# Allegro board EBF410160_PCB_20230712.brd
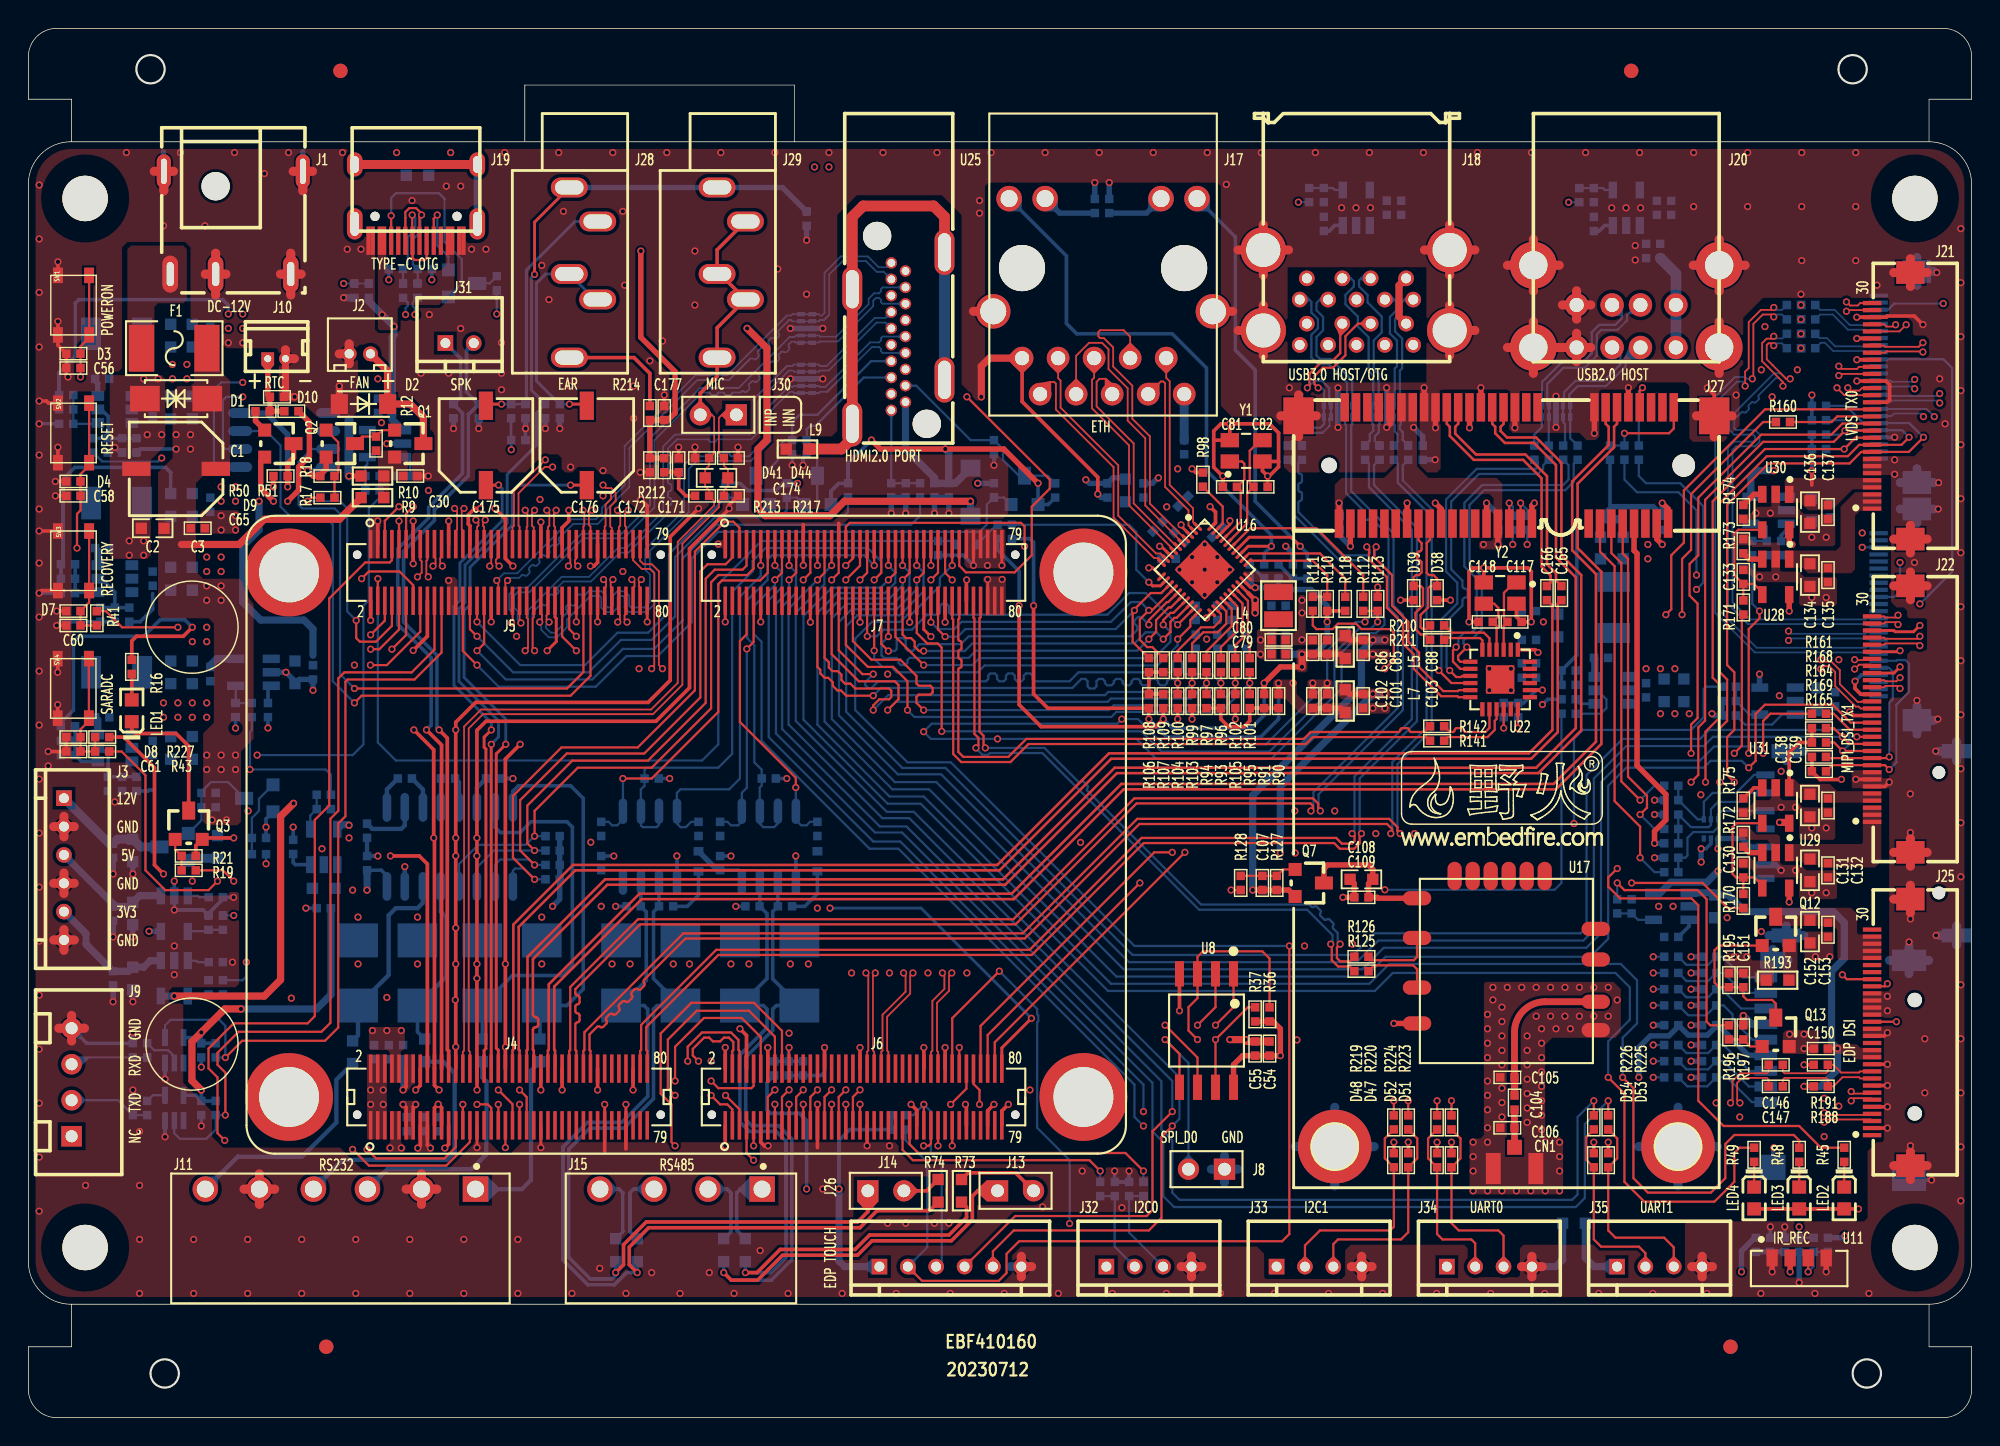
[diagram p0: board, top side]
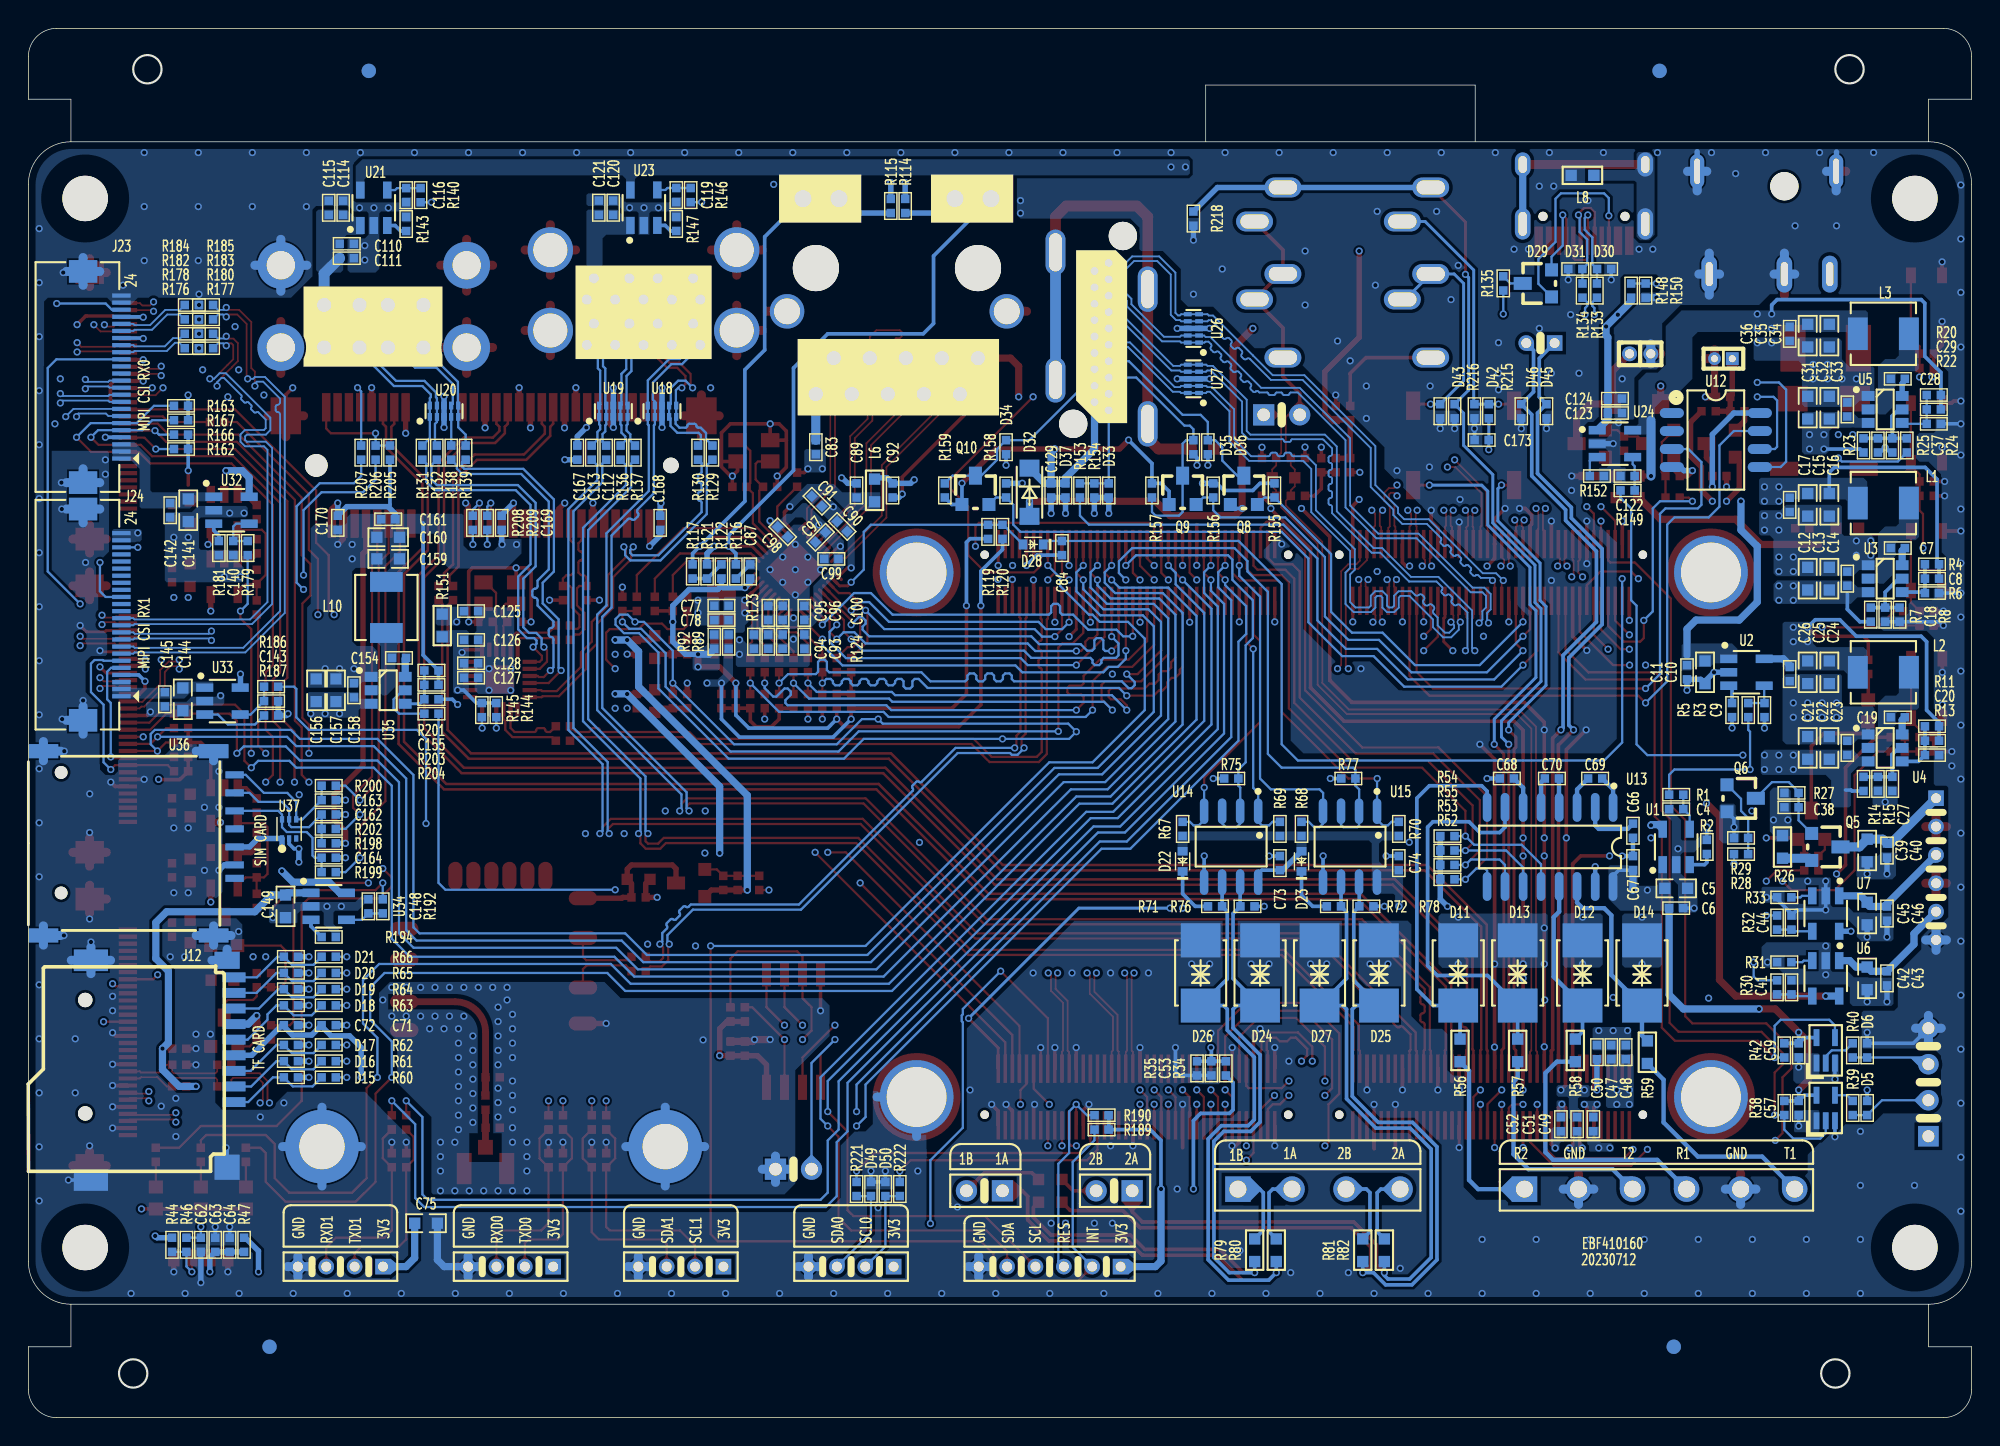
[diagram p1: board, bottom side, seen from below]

Outline 137 x 98 mm; copper layers: TOP, GND02, ART03, POW04, GND05, BOTTOM. Coordinates in mm from the lower left corner of the outline.
Outline path: circle c8.61,95.12 r1 ; circle c9.61,3.12 r1 ; circle c128.61,95.12 r1 ; circle c129.61,3.12 r1 ; 134,90 3,90 arc(0.88,89.12) 0,87 0,11 arc(0.88,8.88) 3,8 134,8 ; 134,90 134,93 137,93 137,96 arc(136.41,97.41) 135,98 2,98 arc(0.59,97.41) 0,96 0,93 3.05,93 3.05,90 ; 134,90 arc(136.12,89.12) 137,87 137,11 arc(136.12,8.88) 134,8 ; 3.05,8 3.05,5 0,5 0,2 arc(0.59,0.59) 2,0 135,0 arc(136.41,0.59) 137,2 137,5 134,5 134,8 ; 35,90 35,94 54,94 54,90

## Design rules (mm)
net group ANTENNA: nets N18056634 N18056637
net group B_DM1: nets B_DM1 HUB_DM1
net group B_DM2: nets B_DM2 HUB_DM2
net group B_DM3: nets B_DM3 HUB_DM3
net group B_DP1: nets B_DP1 HUB_DP1
net group B_DP2: nets B_DP2 HUB_DP2
net group B_DP3: nets B_DP3 HUB_DP3
net group DIFF_MDI0_PHY: nets MDIN0_PHY MDIP0_PHY
net group DIFF_MDI1_PHY: nets MDIN1_PHY MDIP1_PHY
net group DIFF_MDI2_PHY: nets MDIN2_PHY MDIP2_PHY
net group DIFF_MDI3_PHY: nets MDIN3_PHY MDIP3_PHY
net group DIFF_MIC: nets MIC_INN MIC_INP
net group DIFF_PCIE20_REFCLKP: nets PCIE20_REFCLKN PCIE20_REFCLKP
net group DIFF_PCIE20_RXP: nets PCIE20_RXN PCIE20_RXP
net group DIFF_USB3_HOST1_SSRX: nets USB3_HOST1_SSRXN USB3_HOST1_SSRXP
net group DM4: nets DM4 HUB_DM4
net group DP4: nets DP4 HUB_DP4
net group DSI0_TE: nets DSI0_TE N15774097
net group DSI1_TE: nets DSI1_TE N15772454
net group EDP_AUXN: nets EDP_AUXN EDP_TX_AUXN
net group EDP_AUXP: nets EDP_AUXP EDP_TX_AUXP
net group GMAC1_MCLKINOUT_M1: nets GMAC1_MCLKINOUT_M1 PHY_CLKOUT125
net group GMAC1_RXCLK_M1: nets GMAC1_RXCLK_M1 N15599549
net group GMAC1_RXD0_M1: nets GMAC1_RXD0_M1 N15599533
net group GMAC1_RXD1_M1: nets GMAC1_RXD1_M1 N15599537
net group GMAC1_RXD2_M1: nets GMAC1_RXD2_M1 N15599541
net group GMAC1_RXD3_M1: nets GMAC1_RXD3_M1 N15599545
net group GMAC1_RXDV_CRS_M1: nets GMAC1_RXDV_CRS_M1 N15599553
net group HOST1_DM: nets HOST1_DM USB3_HOST1_DM
net group HOST1_DP: nets HOST1_DP USB3_HOST1_DP
net group HP_DET: nets HP_DET N15830941
net group N17975561: nets N17975561 N18091011
net group OTG0_DM: nets OTG0_DM USB_OTG0_DM
net group OTG0_DP: nets OTG0_DP USB_OTG0_DP
net group PCIE20_CLKREQN_M0: nets N16823854 PCIE20_CLKREQN_M0
net group PCIE20_TXN: nets PCIE20_TXN PE_TXN
net group PCIE20_TXP: nets PCIE20_TXP PE_TXP
net group PCIE20_WAKEN_M0: nets N16811933 PCIE20_WAKEN_M0
net group PCIE_PWR_EN: nets N17592220 PCIE_PWR_EN
net group PWM3_IR: nets N17863087 PWM3_IR
net group SDMMC0_CLK: nets N16793151 SDMMC0_CLK
net group SDMMC0_CMD: nets N16793153 SDMMC0_CMD
net group SDMMC0_D0: nets N16793149 SDMMC0_D0
net group SDMMC0_D1: nets N16793157 SDMMC0_D1
net group SDMMC0_D2: nets N16793147 SDMMC0_D2
net group SDMMC0_D3: nets N16793155 SDMMC0_D3
net group SDMMC0_DET: nets N16793300 SDMMC0_DET
net group SIM_CLK0: nets N16980861 SIM_CLK0
net group SIM_DATA0: nets N16980863 SIM_DATA0
net group SIM_RST0: nets N16980859 SIM_RST0
net group SS_TXN: nets SS_TXN USB3_HOST1_SSTXN
net group SS_TXP: nets SS_TXP USB3_HOST1_SSTXP
net group USB2_HOST2_DM: nets N18057325 USB2_HOST2_DM
net group USB2_HOST2_DP: nets N18057335 USB2_HOST2_DP
net group USB2_HOST3_DM: nets N17770942 USB2_HOST3_DM
net group USB2_HOST3_DP: nets N17770939 USB2_HOST3_DP
net group 1V05_AVDD_PHY: nets 1V05_AVDD_PHY 1V05_DVDD_PHY 1V05_PHY
net group 3V3_DVDD_PHY: nets 3V3_DVDD_PHY N15599792 N15600759 N15605755
net group ANALOG: nets HP_SNS HPL_OUT HPR_OUT N15830872 N15838979 N15851038 SPKN_OUT SPKP_OUT
net group CSI_RX_D2N_S0: nets CSI_RX_D2N_S0 CSI_RX_D2N_S1 MIPI_CSI_RX_D2N
net group CSI_RX_D2P_S0: nets CSI_RX_D2P_S0 CSI_RX_D2P_S1 MIPI_CSI_RX_D2P
net group CSI_RX_D3N_S0: nets CSI_RX_D3N_S0 CSI_RX_D3N_S1 MIPI_CSI_RX_D3N
net group CSI_RX_D3P_S0: nets CSI_RX_D3P_S0 CSI_RX_D3P_S1 MIPI_CSI_RX_D3P
net group PWR: nets 3V3_OUT 3V3_WLAN 5V_OUT 12V_OUT HDMI_5V N17750554 N17759502 N17861933 SIM_VDD VCC_RTC

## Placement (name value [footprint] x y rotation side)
C1  220uF  [EC6P3]  10.41 66.93 270 top
C2  10uF  [C0603]  8.76 62.74 180 top
C3  0.1uF  [C0402]  11.94 62.74 0 top
C4  0.1uF  [C0402]  20.83 42.92 0 bottom
C5  10uF  [C0603]  20.83 37.34 180 bottom
C6  0.1uF  [C0402]  20.83 35.94 180 bottom
C7  0.1uF  [C0402]  5.21 61.34 0 bottom
C8  NC  [C0402]  2.79 59.18 0 bottom
C9  0.1uF  [C0402]  14.61 49.91 270 bottom
C10  10uF  [C0603]  18.8 52.58 270 bottom
C11  0.1uF  [C0402]  20.07 52.58 270 bottom
C12  10uF  [C0603]  11.56 59.18 90 bottom
C13  10uF  [C0603]  10.03 59.18 90 bottom
C14  0.1uF  [C0402]  8.76 59.18 90 bottom
C15  22uF  [C0603]  11.56 64.39 270 bottom
C16  22uF  [C0603]  10.03 64.39 270 bottom
C17  0.1uF  [C0402]  12.83 64.39 270 bottom
C18  NC  [C0402]  6.1 56.64 90 bottom
C19  0.1uF  [C0402]  5.21 49.4 0 bottom
C20  NC  [C0402]  2.79 47.75 0 bottom
C21  10uF  [C0603]  11.56 47.24 90 bottom
C22  10uF  [C0603]  10.03 47.24 90 bottom
C23  0.1uF  [C0402]  8.76 47.24 90 bottom
C24  22uF  [C0603]  10.03 52.58 270 bottom
C25  22uF  [C0603]  11.56 52.58 270 bottom
C26  0.1uF  [C0402]  12.83 52.45 270 bottom
C27  NC  [C0402]  5.59 44.7 90 bottom
C28  0.1uF  [C0402]  5.21 73.28 0 bottom
C29  NC  [C0402]  2.67 71.12 0 bottom
C30  0.1uF  [C0402]  26.92 66.42 0 top
C31  10uF  [C0603]  11.56 71.25 90 bottom
C32  10uF  [C0603]  10.03 71.25 90 bottom
C33  0.1uF  [C0402]  8.76 71.12 90 bottom
C34  22uF  [C0603]  10.03 76.33 270 bottom
C35  22uF  [C0603]  11.56 76.33 270 bottom
C36  0.1uF  [C0402]  12.83 76.45 270 bottom
C37  NC  [C0402]  5.59 68.58 90 bottom
C38  0.1uF  [C0402]  12.7 43.05 180 bottom
C39  10uF  [C0603]  7.37 40 270 bottom
C40  0.1uF  [C0402]  5.97 40 270 bottom
C41  0.1uF  [C0402]  12.7 30.35 90 bottom
C42  10uF  [C0603]  7.37 30.99 270 bottom
C43  0.1uF  [C0402]  5.97 30.99 270 bottom
C44  0.1uF  [C0402]  12.7 34.92 90 bottom
C45  10uF  [C0603]  7.37 35.56 270 bottom
C46  0.1uF  [C0402]  5.97 35.56 270 bottom
C47  0.1uF  [C0402]  25.4 25.78 90 bottom
C48  0.1uF  [C0402]  24.38 25.78 90 bottom
C49  0.1uF  [C0402]  26.67 20.7 270 bottom
C50  0.1uF  [C0402]  26.42 25.78 90 bottom
C51  0.1uF  [C0402]  27.81 20.7 90 bottom
C52  0.1uF  [C0402]  28.96 20.7 270 bottom
C53  1uF  [C0402]  53.59 24.64 270 bottom
C54  4.7uF  [C0402]  87.5 26.03 90 top
C55  0.1uF  [C0402]  86.49 26.03 90 top
C56  0.1uF  [C0402]  3.17 74.04 180 top
C57  0.1uF  [C0402]  12.19 21.84 270 bottom
C58  0.1uF  [C0402]  3.17 65.02 180 top
C59  0.1uF  [C0402]  12.19 25.91 270 bottom
C60  0.1uF  [C0402]  3.17 55.88 180 top
C61  0.1uF  [C0402]  3.17 46.99 180 top
C62  NC  [C0402]  124.84 12.19 270 bottom
C63  0.1uF  [C0402]  123.83 12.19 90 bottom
C64  1uF  [C0402]  122.81 12.19 90 bottom
C65  0.1uF  [C0402]  17.78 66.42 180 top
C66  0.1uF  [C0402]  23.88 41.4 270 bottom
C67  4.7uF  [C0402]  23.88 39.11 90 bottom
C68  0.1uF  [C0402]  32.77 45.08 0 bottom
C69  0.1uF  [C0402]  26.54 45.08 180 bottom
C70  0.1uF  [C0402]  29.59 45.08 180 bottom
C71  4.7uF  [C0402]  115.82 27.68 180 bottom
C72  0.1uF  [C0402]  118.49 27.68 180 bottom
C73  0.1uF  [C0402]  48.77 39.11 90 bottom
C74  0.1uF  [C0402]  40.39 39.11 90 bottom
C75  10uF  [C0603]  108.97 13.71 180 bottom
C77  0.1uF  [C0402]  88.14 57.28 0 bottom
C78  4.7uF  [C0402]  88.14 56.26 0 bottom
C79  0.1uF  [C0402]  88.14 53.85 0 top
C80  4.7uF  [C0402]  88.14 54.86 0 top
C81  18pF  [C0402]  84.71 65.66 180 top
C82  18pF  [C0402]  86.87 65.66 0 top
C83  0.1uF  [C0402]  81.48 68.45 270 bottom
C84  0.1uF  [C0402]  64.14 61.34 270 bottom
C85  4.7uF  [C0402]  91.57 54.35 90 top
C86  0.1uF  [C0402]  90.55 54.35 90 top
C87  0.1uF  [C0402]  86.11 59.69 90 bottom
C88  0.1uF  [C0402]  94.11 54.35 270 top
C89  4.7uF  [C0402]  78.61 65.4 90 bottom
C90  0.1uF  [C0402]  79.63 62.86 45 bottom
C91  0.1uF  [C0402]  81.41 64.64 225 bottom
C92  0.1uF  [C0402]  76.07 65.4 270 bottom
C93  4.7uF  [C0402]  83.82 54.74 270 bottom
C94  0.1uF  [C0402]  84.84 54.74 270 bottom
C95  0.1uF  [C0402]  84.84 56.77 90 bottom
C96  4.7uF  [C0402]  83.82 56.77 90 bottom
C97  0.1uF  [C0402]  81.15 62.1 315 bottom
C98  0.1uF  [C0402]  83.82 62.48 225 bottom
C99  0.1uF  [C0402]  80.39 60.58 0 bottom
C100  4.7uF  [C0402]  82.3 56.77 90 bottom
C101  4.7uF  [C0402]  91.57 50.54 90 top
C102  0.1uF  [C0402]  90.55 50.54 90 top
C103  0.1uF  [C0402]  94.11 50.54 270 top
C104  10pF  [C0402]  104.78 22.22 270 top
C105  NC  [C0402]  104.27 24 180 top
C106  NC  [C0402]  104.27 20.45 180 top
C107  0.1uF  [C0402]  87 37.72 90 top
C108  10uF  [C0603]  93.98 37.97 180 top
C109  0.1uF  [C0402]  93.98 36.7 180 top
C110  1uF  [C0402]  114.55 82.8 180 bottom
C111  1uF  [C0402]  114.55 81.79 180 bottom
C112  0.1uF  [C0402]  96.27 68.07 270 bottom
C113  0.1uF  [C0402]  97.28 68.07 270 bottom
C114  10uF  [C0402]  114.81 85.34 90 bottom
C115  0.1uF  [C0402]  115.82 85.34 90 bottom
C116  0.1uF  [C0402]  110.36 86.23 270 bottom
C117  NC  [C0402]  104.78 56.13 0 top
C118  NC  [C0402]  102.74 56.13 0 top
C119  0.1uF  [C0402]  91.32 86.24 270 bottom
C120  10uF  [C0402]  95.77 85.35 90 bottom
C121  0.1uF  [C0402]  96.78 85.35 90 bottom
C122  0.1uF  [C0402]  24.26 66.42 0 bottom
C123  10uF  [C0402]  25.15 70.86 180 bottom
C124  0.1uF  [C0402]  25.15 71.88 180 bottom
C125  0.1uF  [C0402]  105.79 56.89 180 bottom
C126  4.7uF  [C0402]  105.79 54.86 180 bottom
C127  0.1uF  [C0402]  105.79 52.2 180 bottom
C128  0.1uF  [C0402]  105.79 53.21 180 bottom
C129  1uF  [C0402]  64.9 65.4 270 bottom
C130  0.1uF  [C0402]  120.9 38.61 90 top
C131  10uF  [C0603]  125.6 38.61 270 top
C132  0.1uF  [C0402]  126.87 38.61 270 top
C133  0.1uF  [C0402]  120.9 59.31 90 top
C134  10uF  [C0603]  125.6 59.43 270 top
C135  0.1uF  [C0402]  126.87 59.43 270 top
C136  10uF  [C0603]  125.6 63.88 270 top
C137  0.1uF  [C0402]  126.87 63.88 270 top
C138  10uF  [C0603]  125.6 43.18 270 top
C139  0.1uF  [C0402]  126.87 43.18 270 top
C140  0.1uF  [C0402]  122.56 61.34 270 bottom
C141  10uF  [C0603]  125.73 64.01 270 bottom
C142  0.1uF  [C0402]  127 64.01 270 bottom
C143  0.1uF  [C0402]  119.89 50.54 180 bottom
C144  10uF  [C0603]  126.11 50.67 270 bottom
C145  0.1uF  [C0402]  127.38 50.67 270 bottom
C146  0.1uF  [C0402]  123.19 24.89 0 top
C147  0.1uF  [C0402]  123.19 23.37 0 top
C148  0.1uF  [C0402]  113.03 36.07 90 bottom
C149  10uF  [C0603]  118.87 36.07 270 bottom
C150  0.1uF  [C0402]  126.36 26.03 180 top
C151  0.1uF  [C0402]  120.9 30.86 270 top
C152  10uF  [C0603]  125.6 34.29 270 top
C153  0.1uF  [C0402]  126.87 34.42 270 top
C154  0.1uF  [C0402]  110.87 53.59 0 bottom
C155  NC  [C0402]  108.58 51.69 0 bottom
C156  10uF  [C0603]  116.71 51.31 90 bottom
C157  10uF  [C0603]  115.32 51.31 90 bottom
C158  0.1uF  [C0402]  114.05 51.31 90 bottom
C159  22uF  [C0603]  111.63 60.58 0 bottom
C160  22uF  [C0603]  111.63 62.1 0 bottom
C161  0.1uF  [C0402]  111.63 63.37 0 bottom
C162  33pF  [C0402]  115.82 42.54 180 bottom
C163  33pF  [C0402]  115.82 43.56 180 bottom
C164  33pF  [C0402]  115.82 39.5 180 bottom
C165  0.1uF  [C0402]  108.08 58.16 90 top
C166  0.1uF  [C0402]  107.06 58.16 90 top
C167  0.1uF  [C0402]  98.3 68.07 270 bottom
C168  0.1uF  [C0402]  92.46 63.12 270 bottom
C169  4.7uF  [C0402]  103.63 63.12 90 bottom
C170  4.7uF  [C0402]  115.19 63.12 270 bottom
C171  1uF  [C0402]  45.85 67.18 90 top
C172  0.1uF  [C0402]  43.81 67.18 270 top
C173  1uF  [C0402]  34.54 68.96 0 bottom
C174  100pF  [C0603]  48.51 66.29 0 top
C175  220uF  [EC6P3]  32.26 68.58 180 top
C176  220uF  [EC6P3]  39.37 68.58 180 top
C177  0.1uF  [C0402]  44.83 70.86 90 top
CN1  WiFi-Ant  [UFL-3]  104.78 17.57 180 top
D1  SMAJ13CA  [SMA214-CA]  10.41 71.88 180 top
D2  1N4148W  [SOD-123]  23.62 71.5 0 top
D3  KLXES15AAA1  [ES0402]  3.17 75.06 0 top
D4  KLXES15AAA1  [ES0402]  3.17 66.04 0 top
D5  KLXES15AAA1  [ES0402]  7.37 21.84 270 bottom
D6  KLXES15AAA1  [ES0402]  7.37 25.91 270 bottom
D7  KLXES15AAA1  [ES0402]  3.17 56.89 0 top
D8  KLXES15AAA1  [ES0402]  3.17 48 0 top
D9  BAT54C  [SOT23]  17.65 68.71 270 top
D10  KLXES15AAA1  [ES0402]  17.53 72.01 180 top
D11  SMBJ15CA  [SMB-CA]  36.2 31.37 270 bottom
D12  SMBJ15CA  [SMB-CA]  27.43 31.37 270 bottom
D13  SMBJ15CA  [SMB-CA]  32 31.37 270 bottom
D14  SMBJ15CA  [SMB-CA]  23.24 31.37 270 bottom
D15  KLXES15AAA1  [ES0402]  118.49 24 0 bottom
D16  KLXES15AAA1  [ES0402]  118.49 25.14 0 bottom
D17  KLXES15AAA1  [ES0402]  118.49 26.29 0 bottom
D18  KLXES15AAA1  [ES0402]  118.49 29.08 0 bottom
D19  KLXES15AAA1  [ES0402]  118.49 30.22 0 bottom
D20  KLXES15AAA1  [ES0402]  118.49 31.37 0 bottom
D21  KLXES15AAA1  [ES0402]  118.49 32.51 0 bottom
D22  RB521S-30  [SOD523]  55.63 39.24 90 bottom
D23  RB521S-30  [SOD523]  47.24 39.24 90 bottom
D24  SMBJ6.5CA  [SMB-CA]  50.16 31.37 270 bottom
D25  SMBJ6.5CA  [SMB-CA]  41.78 31.37 270 bottom
D26  SMBJ6.5CA  [SMB-CA]  54.36 31.37 270 bottom
D27  SMBJ6.5CA  [SMB-CA]  45.97 31.37 270 bottom
D28  RB521S-30  [SOD523]  66.17 61.59 0 bottom
D29  BAT54A  [SOT23]  30.61 80.01 90 bottom
D30  KLXES15AAA1  [ES0402]  25.91 81.02 0 bottom
D31  KLXES15AAA1  [ES0402]  27.94 81.02 180 bottom
D32  1N5819W  [SOD-123]  66.42 65.28 90 bottom
D33  KLXES15AAA1  [ES0402]  60.83 65.4 90 bottom
D34  KLXES15AAA1  [ES0402]  68.07 68.45 90 bottom
D35  KLXES15AAA1  [ES0402]  54.86 68.45 90 bottom
D36  KLXES15AAA1  [ES0402]  53.85 68.45 90 bottom
D37  KLXES15AAA1  [ES0402]  63.88 65.4 90 bottom
D38  KLXES15AAA1  [ES0402]  99.31 58.16 90 top
D39  KLXES15AAA1  [ES0402]  97.66 58.16 90 top
D41  KLXES15AAA1  [ES0402]  47.5 67.69 0 top
D42  KLXES15AAA1  [ES0402]  35.05 70.99 90 bottom
D43  KLXES15AAA1  [ES0402]  37.47 70.99 90 bottom
D44  KLXES15AAA1  [ES0402]  49.53 67.69 180 top
D45  KLXES15AAA1  [ES0402]  29.97 70.99 90 bottom
D46  KLXES15AAA1  [ES0402]  31.75 70.99 90 bottom
D47  KLXES15AAA1  [ES0402]  97.28 18.16 270 top
D48  KLXES15AAA1  [ES0402]  96.27 18.16 270 top
D49  KLXES15AAA1  [ES0402]  77.6 16.13 270 bottom
D50  KLXES15AAA1  [ES0402]  76.58 16.13 270 bottom
D51  KLXES15AAA1  [ES0402]  100.33 18.16 270 top
D52  KLXES15AAA1  [ES0402]  99.31 18.16 270 top
D53  KLXES15AAA1  [ES0402]  111.38 18.16 270 top
D54  KLXES15AAA1  [ES0402]  110.36 18.16 270 top
F1  SMD1812P200TF16  [F1812]  10.29 75.44 0 top
H1  -  [NPTH_M3]  4 86 0 top
H2  -  [NPTH_M3]  4 12 0 top
H3  -  [NPTH_M3]  133 12 0 top
H4  -  [NPTH_M3]  133 86 0 top
J1  DC-044A-20A  [DC_IN_TH_3P_10R1X11R6]  14.45 85.16 270 top
J2  A1501WV-2P  [ZH1P5MM_TH_2P]  23.37 75.04 180 top
J3  PH-6A  [PH-1X6-2P0]  2.51 38.69 270 top
J4  -  [SGDBM-05-80P-H10]  33.88 22.62 0 top
J5  -  [SGDBF-05-80P-H30]  33.88 59.62 180 top
J6  -  [SGDBM-05-80P-H10]  58.88 22.62 0 top
J7  -  [SGDBF-05-80P-H30]  58.88 59.62 180 top
J8  1X2PIN-M  [DIP-1X2-2P54]  83.06 17.52 180 top
J9  XH-4A  [XH2P54-4P]  3.05 23.66 90 top
J10  1.25T-2A  [GH1P25_TH_2P]  17.5 74.7 0 top
J11  CON6  [DB2ERC-3P81-6P]  22 16.12 180 top
J12  TF_Card  [TFCARD]  132.99 25.46 270 bottom
J13  1X2PIN-M  [DIP-1X2-2P54]  69.6 16 0 top
J14  1X2PIN-M  [DIP-1X2-2P54]  60.45 16 0 top
J15  WJ15EDGRC-3.81-4P  [DB2ERC-3P81-4P]  46.01 16.12 180 top
J17  -  [HY911130A]  75.77 81.09 0 top
J18  USB3D0_USB2D0-A-D  [USB3D0-AF-18P]  93.63 78.87 180 top
J19  TYPE-C  [TYPE-C-31-M-12]  27.33 83.3 180 top
J20  -  [USB-A-D]  112.65 81.99 0 top
J21  FPC_0R5_30P_D  [FPC-30P-0P5]  131.33 71.37 90 top
J22  FPC_0R5_30P_D  [FPC-30P-0P5]  131.33 49.27 90 top
J23  FPC_0P5_24P_D  [FPC_24P_0P5]  131.79 73.41 90 bottom
J24  FPC_0P5_24P_D  [FPC_24P_0P5]  131.79 56.64 90 bottom
J25  FPC_0R5_30P_D  [FPC-30P-0P5]  131.33 27.18 90 top
J26  PH-6A  [PH-1X6-2P0]  65 10.65 0 top
J27  MINI-PCIE  [PCIE_52P]  104.2 67.17 180 top
J28  PJ-325C5-G  [EAR_JACK]  39.04 80.68 270 top
J29  PJ-325C5-R  [EAR_JACK]  49.45 80.68 270 top
J30  1X2PIN-M  [DIP-1X2-2P54]  48.64 70.74 180 top
J31  PH  [PH-1X2-2P0_L]  30.4 75.8 0 top
J32  PH-4A  [PH-1X4-2P0]  79 10.65 0 top
J33  PH-4A  [PH-1X4-2P0]  91 10.65 0 top
J34  PH-4A  [PH-1X4-2P0]  103 10.65 0 top
J35  PH-4A  [PH-1X4-2P0]  115 10.65 0 top
L1  3.3uH  [L4520]  6.22 64.51 0 bottom
L2  3.3uH  [L4520]  6.22 52.58 0 bottom
L3  3.3uH  [L4520]  6.22 76.45 0 bottom
L4  2.2uH  [L2520]  88.14 57.28 270 top
L5  100R 100MHz  [L0603]  92.84 54.35 90 top
L6  100R 100MHz  [L0603]  77.34 65.4 90 bottom
L7  100R 100MHz  [L0603]  92.84 50.54 90 top
L8  120R 100MHz  [L0603]  27.43 87.63 0 bottom
L9  330R 100MHz  [L0603]  54.23 68.32 180 top
L10  3.3uH  [L4520]  111.76 57.15 90 bottom
LED1  RED  [LED0603]  7.29 49.86 270 top
LED2  BLUE  [LED0603]  128.02 15.49 90 top
LED3  BLUE  [LED0603]  124.84 15.49 90 top
LED4  BLUE  [LED0603]  121.67 15.49 90 top
NOREF  -  []  0 49 0 top
NOREF#2  -  []  0.51 38.69 90 top
NOREF#3  -  []  136.49 73.41 90 top
NOREF#4  -  []  15.38 41.12 90 top
NOREF#5  -  []  68.5 8 90 top
NOREF#6  -  []  0.51 23.66 90 top
NOREF#7  -  []  68.5 0 90 top
NOREF#8  -  [unnamed#2]  113 95 0 top
NOREF#9  -  []  4 12 0 top
NOREF#10  -  []  0 49 0 top
NOREF#11  -  []  6.83 8 90 top
NOREF#12  -  []  0 49 0 top
NOREF#13  -  []  135.98 71.38 90 top
NOREF#14  -  []  0 13.6 0 top
NOREF#15  -  []  135.98 49.28 90 top
NOREF#16  -  []  122.49 31.06 90 top
NOREF#17  -  []  0 14.29 0 top
NOREF#18  -  []  134.57 12.28 0 top
NOREF#19  -  []  0 49 0 top
NOREF#20  -  []  0 49 0 top
NOREF#21  -  []  135.98 27.18 90 top
NOREF#22  -  []  0 49 0 top
NOREF#23  -  []  0 14.83 0 top
NOREF#24  -  []  4 12 0 top
NOREF#25  -  []  122.46 45.34 90 top
NOREF#26  -  []  0 78.37 0 top
NOREF#27  -  []  0 49 0 top
NOREF#28  -  []  0 -0.29 0 top
NOREF#29  -  []  4 12 90 top
NOREF#30  -  []  0 49 0 top
NOREF#31  -  [unnamed#2]  120 5 0 top
NOREF#32  -  []  0 12.03 0 top
NOREF#33  -  []  22.08 0 90 top
NOREF#34  -  []  0 13.88 0 top
NOREF#35  -  [unnamed#2]  22 95 0 top
NOREF#36  -  []  0 16.34 0 top
NOREF#37  -  []  0 78.12 0 top
NOREF#38  -  []  68.5 8 90 top
NOREF#39  -  []  136.23 9 0 top
NOREF#40  -  []  0 17.63 0 top
NOREF#41  -  []  0 49 0 top
NOREF#42  -  []  136.49 56.64 90 top
NOREF#43  -  [unnamed#2]  21 5 0 top
NOREF#44  -  []  133 12 90 top
NOREF#45  -  []  0 49 0 top
NOREF#46  -  [unnamed#2]  113 95 180 bottom
NOREF#47  -  [unnamed#2]  120 5 180 bottom
NOREF#48  -  [unnamed#2]  21 5 180 bottom
NOREF#49  -  [unnamed#2]  22 95 180 bottom
Q1  AO3407  [SOT23]  26.81 68.71 270 top
Q2  SS8050  [SOT23]  21.98 68.71 270 top
Q3  SS8050  [SOT23]  11.3 41.78 0 top
Q5  AO3407  [SOT23]  10.29 40.26 270 bottom
Q6  SS8050  [SOT23]  16.26 43.69 270 bottom
Q7  AO3407  [SOT23]  90.3 37.72 270 top
Q8  2SK3018  [SOT23]  51.31 65.4 180 bottom
Q9  2SK3018  [SOT23]  55.63 65.4 180 bottom
Q10  2SK3018  [SOT23]  70.23 65.4 180 bottom
Q12  AO3407  [SOT23]  123.19 34.29 0 top
Q13  SS8050  [SOT23]  123.19 27.18 0 top
R1  1K  [R0402]  20.83 43.94 180 bottom
R2  3.4K  [R0402]  18.67 40.26 90 bottom
R3  1K  [R0402]  15.75 49.91 90 bottom
R4  100K  [R0402]  2.79 60.2 0 bottom
R5  6.8K  [R0402]  16.89 49.91 270 bottom
R6  30K  [R0402]  2.79 58.16 180 bottom
R7  140K  [R0402]  7.11 56.64 90 bottom
R8  20K  [R0402]  5.08 56.64 270 bottom
R9  NC  [R0603]  24.26 64.9 0 top
R10  0R  [R0603]  24.26 66.42 0 top
R11  115K  [R0402]  2.79 48.77 0 bottom
R12  20K  [R0402]  24.51 68.71 90 top
R13  20K  [R0402]  2.79 46.73 180 bottom
R14  140K  [R0402]  7.62 44.7 90 bottom
R15  20K  [R0402]  6.6 44.7 270 bottom
R16  4.7K  [R0402]  7.29 52.96 270 top
R17  1K  [R0402]  21.08 64.9 0 top
R18  10K  [R0402]  21.08 66.42 180 top
R19  1K  [R0402]  11.3 38.61 180 top
R20  115K  [R0402]  2.67 72.13 0 bottom
R21  10K  [R0402]  11.3 39.62 0 top
R22  20K  [R0402]  2.67 70.1 180 bottom
R23  NC  [R0402]  7.62 68.58 90 bottom
R24  1K  [R0402]  4.57 68.58 90 bottom
R25  NC  [R0402]  6.6 68.58 270 bottom
R26  0R  [R0603]  13.34 40.26 270 bottom
R27  20K  [R0402]  12.7 44.07 180 bottom
R28  510R  [R0402]  16.26 39.75 180 bottom
R29  10K  [R0402]  16.26 40.89 0 bottom
R30  1K  [R0402]  13.72 30.35 270 bottom
R31  6.8K  [R0402]  13.21 32.13 0 bottom
R32  1K  [R0402]  13.72 34.92 270 bottom
R33  6.8K  [R0402]  13.21 36.7 0 bottom
R34  15K  [R0402]  52.58 24.64 90 bottom
R35  10K  [R0402]  54.61 24.64 270 bottom
R36  10K  [R0402]  87.5 28.45 90 top
R37  10K  [R0402]  86.49 28.45 90 top
R38  10K  [R0402]  13.21 21.84 270 bottom
R39  510R  [R0402]  8.38 21.84 90 bottom
R40  510R  [R0402]  8.38 25.91 90 bottom
R41  100R  [R0402]  4.83 56.39 90 top
R42  10K  [R0402]  13.21 25.91 270 bottom
R43  100R  [R0402]  5.21 46.99 0 top
R44  10K  [R0402]  126.87 12.19 270 bottom
R45  470R  [R0402]  128.02 18.54 90 top
R46  22R  [R0402]  125.86 12.19 270 bottom
R47  22R  [R0402]  121.79 12.19 90 bottom
R48  470R  [R0402]  124.84 18.54 90 top
R49  470R  [R0402]  121.67 18.54 90 top
R50  0R  [R0402]  16.51 70.99 0 top
R51  NC  [R0402]  18.54 70.99 0 top
R52  10K  [R0402]  36.96 37.97 180 bottom
R53  10K  [R0402]  36.96 38.99 180 bottom
R54  10K  [R0402]  36.96 41.02 180 bottom
R55  10K  [R0402]  36.96 40 180 bottom
R56  0R  [R0603]  36.07 25.91 270 bottom
R57  0R  [R0603]  32 25.91 270 bottom
R58  0R  [R0603]  27.94 25.91 270 bottom
R59  0R  [R0603]  22.86 25.78 270 bottom
R60  22R  [R0402]  115.82 24 0 bottom
R61  22R  [R0402]  115.82 25.14 0 bottom
R62  22R  [R0402]  115.82 26.29 0 bottom
R63  22R  [R0402]  115.82 29.08 0 bottom
R64  22R  [R0402]  115.82 30.22 0 bottom
R65  22R  [R0402]  115.82 31.37 0 bottom
R66  0R  [R0402]  115.82 32.51 0 bottom
R67  10K  [R0402]  55.63 41.53 90 bottom
R68  10K  [R0402]  47.24 41.53 90 bottom
R69  10K  [R0402]  48.77 41.53 90 bottom
R70  10K  [R0402]  40.39 41.53 90 bottom
R71  4.7K  [R0402]  53.34 36.07 180 bottom
R72  4.7K  [R0402]  44.96 36.07 180 bottom
R73  120R  [R0603]  65.79 16 90 top
R74  120R  [R0603]  64.14 16 90 top
R75  10K  [R0402]  52.2 45.08 0 bottom
R76  4.7K  [R0402]  51.05 36.07 180 bottom
R77  10K  [R0402]  43.94 45.08 0 bottom
R78  4.7K  [R0402]  42.67 36.07 180 bottom
R79  0R  [R0603]  50.55 11.81 90 bottom
R80  0R  [R0603]  49.02 11.81 90 bottom
R81  0R  [R0603]  42.93 11.81 90 bottom
R82  0R  [R0603]  41.4 11.81 90 bottom
R89  NC  [R0402]  87.63 54.74 270 bottom
R90  NC  [R0402]  88.14 50.54 270 top
R91  0R  [R0402]  87.12 50.54 90 top
R92  0R  [R0402]  88.65 54.74 270 bottom
R93  4.7K  [R0402]  84.07 50.54 90 top
R94  4.7K  [R0402]  83.06 50.54 90 top
R95  4.7K  [R0402]  86.11 50.54 90 top
R96  22R  [R0402]  84.07 53.08 90 top
R97  22R  [R0402]  83.06 53.08 90 top
R98  2.49K  [R0402]  82.8 66.17 90 top
R99  22R  [R0402]  82.04 53.08 90 top
R100  22R  [R0402]  81.03 53.08 90 top
R101  22R  [R0402]  86.11 53.08 90 top
R102  22R  [R0402]  85.09 53.08 90 top
R103  4.7K  [R0402]  82.04 50.54 270 top
R104  4.7K  [R0402]  81.03 50.54 270 top
R105  4.7K  [R0402]  85.09 50.54 270 top
R106  NC  [R0402]  78.99 50.54 90 top
R107  0R  [R0402]  80.01 50.54 270 top
R108  4.7K  [R0402]  78.99 53.08 90 top
R109  4.7K  [R0402]  80.01 53.08 90 top
R110  4.7K  [R0402]  91.57 57.4 90 top
R111  NC  [R0402]  90.55 57.4 90 top
R112  0R  [R0402]  94.11 57.4 90 top
R113  NC  [R0402]  95.12 57.4 90 top
R114  510R  [R0402]  75.18 85.47 90 bottom
R115  510R  [R0402]  76.2 85.47 90 bottom
R116  4.7K  [R0402]  87.12 59.69 270 bottom
R117  4.7K  [R0402]  90.17 59.69 270 bottom
R118  4.7K  [R0402]  92.84 57.4 270 top
R119  NC  [R0402]  69.34 62.48 90 bottom
R120  10K  [R0402]  68.33 62.48 90 bottom
R121  0R  [R0402]  89.15 59.69 270 bottom
R122  NC  [R0402]  88.14 59.69 270 bottom
R123  0R  [R0402]  85.85 54.74 270 bottom
R124  0R  [R0402]  82.3 54.74 90 bottom
R125  2.2R  [R0402]  93.98 31.49 0 top
R126  2.2R  [R0402]  93.98 32.51 0 top
R127  10K  [R0402]  88.01 37.72 90 top
R128  510R  [R0402]  85.47 37.72 90 top
R129  2.2R  [R0402]  88.77 68.07 270 bottom
R130  2.2R  [R0402]  89.79 68.07 270 bottom
R131  2.2R  [R0402]  109.22 68.07 270 bottom
R132  2.2R  [R0402]  108.2 68.07 270 bottom
R133  2.2R  [R0402]  26.42 79.5 270 bottom
R134  2.2R  [R0402]  27.43 79.5 270 bottom
R135  100R  [R0402]  33.02 80.01 270 bottom
R136  2.2R  [R0402]  95.25 68.07 270 bottom
R137  2.2R  [R0402]  94.23 68.07 270 bottom
R138  2.2R  [R0402]  107.19 68.07 270 bottom
R139  2.2R  [R0402]  106.17 68.07 270 bottom
R140  1K  [R0402]  109.35 86.23 90 bottom
R141  2.2R  [R0402]  99.31 47.75 180 top
R142  2.2R  [R0402]  99.31 48.77 180 top
R143  3.4K  [R0402]  110.36 84.2 90 bottom
R144  100K  [R0402]  104.01 49.91 270 bottom
R145  100K  [R0402]  105.03 49.91 270 bottom
R146  1K  [R0402]  90.31 86.24 90 bottom
R147  3.4K  [R0402]  91.32 84.21 90 bottom
R148  10K  [R0402]  24 79.5 90 bottom
R149  1K  [R0402]  24.26 65.4 180 bottom
R150  15K  [R0402]  22.99 79.5 270 bottom
R151  0R  [R0603]  107.82 55.88 270 bottom
R152  6.8K  [R0402]  26.42 66.42 180 bottom
R153  1K  [R0402]  62.87 65.4 90 bottom
R154  100K  [R0402]  61.85 65.4 270 bottom
R155  27K  [R0402]  49.15 65.4 270 bottom
R156  10K  [R0402]  53.47 65.4 270 bottom
R157  2.2K  [R0402]  57.78 65.4 270 bottom
R158  10K  [R0402]  68.07 65.4 270 bottom
R159  2.2K  [R0402]  72.39 65.4 90 bottom
R160  0R  [R0402]  123.7 70.23 0 top
R161  0R  [R0402]  126.24 49.66 0 top
R162  10K  [R0402]  126.24 68.32 0 bottom
R163  10K  [R0402]  126.24 71.37 0 bottom
R164  10K  [R0402]  126.24 47.62 0 top
R165  10K  [R0402]  126.24 45.59 0 top
R166  10K  [R0402]  126.24 69.34 0 bottom
R167  10K  [R0402]  126.24 70.36 0 bottom
R168  10K  [R0402]  126.24 48.64 0 top
R169  10K  [R0402]  126.24 46.61 0 top
R170  1K  [R0402]  120.9 36.45 90 top
R171  1K  [R0402]  120.9 57.15 90 top
R172  6.8K  [R0402]  120.9 40.77 90 top
R173  6.8K  [R0402]  120.9 61.47 90 top
R174  6.8K  [R0402]  120.9 63.88 270 top
R175  6.8K  [R0402]  120.9 43.18 270 top
R176  0R  [R0402]  125.48 75.44 0 bottom
R177  NC  [R0402]  124.47 75.44 180 bottom
R178  0R  [R0402]  125.48 76.45 0 bottom
R179  1K  [R0402]  121.54 61.34 90 bottom
R180  NC  [R0402]  124.48 76.45 180 bottom
R181  6.8K  [R0402]  123.57 61.34 270 bottom
R182  0R  [R0402]  125.48 77.47 0 bottom
R183  NC  [R0402]  124.48 77.47 180 bottom
R184  0R  [R0402]  125.48 78.48 0 bottom
R185  NC  [R0402]  124.48 78.48 180 bottom
R186  1K  [R0402]  119.89 51.56 0 bottom
R187  6.8K  [R0402]  119.89 49.53 180 bottom
R188  NC  [R0402]  126.36 23.37 0 top
R189  10K  [R0402]  61.34 20.32 0 bottom
R190  10K  [R0402]  61.34 21.33 0 bottom
R191  NC  [R0402]  126.36 24.89 0 top
R192  1K  [R0402]  112.01 36.07 270 bottom
R193  0R  [R0603]  123.32 30.86 0 top
R194  6.8K  [R0402]  115.82 33.91 180 bottom
R195  20K  [R0402]  119.89 30.86 270 top
R196  1K  [R0402]  119.89 27.18 270 top
R197  10K  [R0402]  120.9 27.18 90 top
R198  15K  [R0402]  115.82 40.51 0 bottom
R199  0R  [R0402]  115.82 38.48 0 bottom
R200  0R  [R0402]  115.82 44.58 0 bottom
R201  100K  [R0402]  108.58 52.7 0 bottom
R202  0R  [R0402]  115.82 41.53 0 bottom
R203  30K  [R0402]  108.58 50.67 180 bottom
R204  0R  [R0402]  108.58 49.66 0 bottom
R205  4.7K  [R0402]  111.51 68.07 90 bottom
R206  22R  [R0402]  112.52 68.07 90 bottom
R207  22R  [R0402]  113.54 68.07 90 bottom
R208  100R  [R0402]  105.66 63.12 270 bottom
R209  100R  [R0402]  104.65 63.12 270 bottom
R210  2.2R  [R0402]  99.31 55.88 0 top
R211  2.2R  [R0402]  99.31 54.86 0 top
R212  120R  [R0402]  44.83 67.18 270 top
R213  2.2K  [R0402]  47.5 65.02 0 top
R214  10K  [R0402]  43.81 70.86 90 top
R215  22R  [R0402]  34.04 70.99 90 bottom
R216  0R  [R0402]  36.45 70.99 270 bottom
R217  2.2K  [R0402]  49.53 65.02 0 top
R218  0R  [R0402]  54.86 84.58 270 bottom
R219  510R  [R0402]  96.27 20.83 90 top
R220  510R  [R0402]  97.28 20.83 90 top
R221  510R  [R0402]  78.61 16.13 90 bottom
R222  510R  [R0402]  75.56 16.13 90 bottom
R223  510R  [R0402]  100.33 20.83 90 top
R224  510R  [R0402]  99.31 20.83 90 top
R225  510R  [R0402]  111.38 20.83 90 top
R226  510R  [R0402]  110.36 20.83 90 top
R227  10K  [R0402]  5.21 48 0 top
SS1  M2.5X4mm  [SMTSO-M2R5]  18.38 22.62 0 top
SS2  M2.5X4mm  [SMTSO-M2R5]  74.38 22.62 0 top
SS3  M2.5X4mm  [SMTSO-M2R5]  18.38 59.62 0 top
SS4  M2.5X4mm  [SMTSO-M2R5]  74.38 59.62 0 top
SS5  M2X3mm  [T3R2-5R2_TOPSMT]  92.1 19.12 0 top
SS6  M2X3mm  [T3R2-5R2_TOPSMT]  116.3 19.12 0 top
SW1  SW_PB_ESW  [SW_3_2X4_2]  3.18 78.48 90 top
SW2  SW_PB_ESW  [SW_3_2X4_2]  3.18 69.46 90 top
SW3  SW_PB_ESW  [SW_3_2X4_2]  3.18 60.44 90 top
SW4  SW_PB_ESW  [SW_3_2X4_2]  3.17 51.44 90 top
U1  MT9700  [SOT23-5]  20.83 40.26 180 bottom
U2  MT9700  [SOT23-5]  15.88 52.58 270 bottom
U3  TP6327GS6  [SOT23_6]  6.1 59.18 270 bottom
U4  TP6327GS6  [SOT23_6]  6.1 47.24 270 bottom
U5  TP6327GS6  [SOT23_6]  6.1 71.12 270 bottom
U6  MT9700  [SOT23-5]  10.29 30.99 0 bottom
U7  MT9700  [SOT23-5]  10.29 35.56 0 bottom
U8  NC  [SOIC8-208]  83.06 27.3 270 top
U9  74LVC1G125GW  [SOT-353]  10.29 21.84 180 bottom
U10  74LVC1G125GW  [SOT-353]  10.29 25.91 180 bottom
U11  IRM-V838M3-C/TR1  [SMD4-6R80X2R50]  124.84 11.27 180 top
U12  RX8010SJ  [SOP-8]  18.03 68.96 270 bottom
U13  MAX3232CSE  [SOIC16]  29.72 40.26 270 bottom
U14  MAX3485  [SOP8]  52.21 40.28 0 bottom
U15  MAX3485  [SOP8]  43.82 40.28 0 bottom
U16  JL2101-N040C  [QFP_40P_R]  82.93 59.82 315 top
U17  TL8821CUB  [RL-UM02WBS-8723BU]  104.2 31.31 180 top
U18  RCLAMP0524P  [USON_10]  92.33 70.99 180 bottom
U19  RCLAMP0524P  [USON_10]  95.76 70.99 180 bottom
U20  RCLAMP0524P  [USON_10]  107.7 70.99 180 bottom
U21  MT9700  [SOT23-5]  112.65 85.34 180 bottom
U22  CH334F  [QFN24]  103.76 52.07 270 top
U23  MT9700  [SOT23-5]  93.61 85.35 180 bottom
U24  MT9700  [SOT23-5]  25.15 68.71 270 bottom
U25  HDMI-001C  [HDMI-SMD]  61.34 76.15 90 top
U26  RCLAMP0524P  [USON_10]  54.86 76.83 90 bottom
U27  RCLAMP0524P  [USON_10]  54.86 73.28 90 bottom
U28  MT9700  [SOT23-5]  123.19 59.31 180 top
U29  MT9700  [SOT23-5]  123.19 38.61 180 top
U30  MT9700  [SOT23-5]  123.19 63.88 180 top
U31  MT9700  [SOT23-5]  123.19 43.18 180 top
U32  MT9700  [SOT23-5]  122.68 64.01 270 bottom
U33  MT9700  [SOT23-5]  123.32 50.54 270 bottom
U34  MT9700  [SOT23-5]  115.82 36.07 270 bottom
U35  TP6327GS6  [SOT23_6]  111.63 51.31 270 bottom
U36  SIM-7-1  [NANO_SIM]  129.2 40.51 270 bottom
U37  NUP5120X6T1G  [SOT563]  118.62 41.53 180 bottom
Y1  25MHz  [3225]  85.85 68.2 0 top
Y2  12MHz  [3225]  103.76 58.16 180 top

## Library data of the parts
C1 C175 C176 = CAP
C2-C75 C77-C111 C114-C145 C148-C164 C167-C174 C177 = CAP_NP
C112 C113 C146 C147 C165 C166 = CAP_NP: signal model: CAP_NP_C0402_DISCRETE_0.1UF_0.1uF
CN1 = WIFI_ANT
D1 D3-D8 D10-D21 D24-D27 D30 D31 D33-D39 D41-D54 = DIODE BI-DIR TRIG
D2 = DIODE
D9 = BAT54C
D22 D23 D28 D32 = DIODE_SCHTKY
D29 = BAT54A
F1 = FUSE
H1-H4 SS1-SS6 = SPACER
J1 = DC-044A-20A
J2 = A1501WV-2P
J3 J26 = 1X6PIN
J4-J7 = SGDBM-05-80P-H10
J8 J13 J14 J30 = B2S
J9 J15 = CON4
J10 = 1.25T-2A
J11 = CON6
J12 = TF_Card
J17 = HY911130A
J18 = USB3D0_USB2D0-A-D
J19 = TYPE-C-31-M-12
J20 = USB-A-D
J21 J22 J25 = FPC-30P
J23 J24 = FPC-24P
J27 = MINI-PCIE
J28 J29 = MIC_JACK
J31 = 1X2PIN
J32-J35 = 1X4PIN
L1-L4 L10 = IND
L5-L9 = BEAD
LED1-LED4 = LED
Q1 Q5 Q7 Q12 = MOSFET_P
Q2 Q3 Q6 Q13 = NPN
Q8-Q10 = 2SK3018
R1-R45 R48 R49 R51-R59 R67-R82 R89 R90 R93-R95 R98 R103-R106 R108-R111 R113-R120 R122 R127 R128 R135 R140 R143-R159 R162-R175 R179 R181 R186-R198 R201 R203 R205 R208 R209 R212-R214 R217 R219-R227 = RES
R46 R47 R60-R65 R96 R97 R99-R102 R206 R207 R215 = RES: signal model: RES_R0402_DISCRETE_22R_22R
R50 R66 R91 R92 R107 R112 R121 R123 R124 R160 R161 R176 R178 R182 R184 R199 R200 R202 R204 R216 R218 = RES: signal model: RES_R0402_DISCRETE_0R_0R
R125 R126 R129-R134 R136-R139 R141 R142 R210 R211 = RES: signal model: RES_R0402_DISCRETE_2.2R_2.2R
R177 R180 R183 R185 = RES: signal model: RES_R0402_DISCRETE_NC_NC
SW1-SW4 = SW_PB_ESW
U1 U2 U6 U7 U21 U23 U24 U28-U34 = MT9700
U3-U5 U35 = TP6327GS6
U8 = W25QXX_8P
U9 U10 = 74LVC1G125
U11 = IRM-V838M3-C/TR1
U12 = RX8010SJ
U13 = MAX3232CSE
U14 U15 = TJA1057GT3
U16 = RTL8211F
U17 = RTL8723
U18-U20 = RCLAMP0524P
U22 = CH334F
U25 = HDMI-001C
U26 U27 = RCLAMP0524P: signal model: RCLAMP0524P_USON_10_RCLAMP0524P_RCLAMP0524P
U36 = SIM-7-1
U37 = NUP5120-D
Y1 Y2 = CRYSTAL_4P

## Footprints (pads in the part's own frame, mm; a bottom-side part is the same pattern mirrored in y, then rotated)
3225
  rect 1.3x1 smd: 1(-1.15,-0.75) 2(1.15,-0.75) 3(1.15,0.75) 4(-1.15,0.75)
C0402
  rect 0.599x0.599 smd: 1(-0.5,0) 2(0.5,0)
C0603
  rect 0.8x0.8 smd: 1(-0.8,0) 2(0.8,0)
DB2ERC-3P81-4P
  rect 1.8x1.8 hole 1.2: 1(-5.715,0)
  round 1.8 hole 1.2: 2(-1.905,0) 3(1.905,0) 4(5.715,0)
DB2ERC-3P81-6P
  rect 1.8x1.8 hole 1.2: 1(-9.525,0)
  round 1.8 hole 1.2: 2(-5.715,0) 3(-1.905,0) 4(1.905,0) 5(5.715,0) 6(9.525,0)
DC_IN_TH_3P_10R1X11R6
  round 1.999 hole 1.999 unplated: (-1.699,-1.25)
  oval 2.4x1.001 hole 1.801x0.399: 1(-2.751,-4.9) 5(-2.751,4.9)
  oval 2.601x1.1 hole 1.699x0.5: 2(4.501,-1.25) 3(4.501,4.049) 4(4.501,-4.45)
DIP-1X2-2P54
  rect 1.5x1.5 hole 0.9: 1(-1.27,0)
  round 1.5 hole 0.9: 2(1.27,0)
EAR_JACK
  oval 1.4x2.6 hole 1x2: 1(-6.1,-0.9) 2(-3.7,1.1) 3(1.8,1.1) 4(5.9,-0.9) 5(0,-0.9)
EC6P3
  rect 1.001x1.999 smd: 1(0,2.8) 2(0,-2.8)
ES0402
  rect 0.599x0.599 smd: 1(-0.5,0) 2(0.5,0)
F1812
  rect 1.78x3.3 smd: 1(-2.305,0) 2(2.305,0)
FPC-30P-0P5
  rect 0.3x1.3 smd: 1(-7.25,1.35) 2(-6.75,1.35) 3(-6.25,1.35) 4(-5.75,1.35) 5(-5.25,1.35) 6(-4.75,1.35) 7(-4.25,1.35) 8(-3.75,1.35) 9(-3.25,1.35) 10(-2.75,1.35) 11(-2.25,1.35) 12(-1.75,1.35) 13(-1.25,1.35) 14(-0.75,1.35) 15(-0.25,1.35) 16(0.25,1.35) 17(0.75,1.35) 18(1.25,1.35) 19(1.75,1.35) 20(2.25,1.35) 21(2.75,1.35) 22(3.25,1.35) 23(3.75,1.35) 24(4.25,1.35) 25(4.75,1.35) 26(5.25,1.35) 27(5.75,1.35) 28(6.25,1.35) 29(6.75,1.35) 30(7.25,1.35)
  rect 1.6x2 smd: 31(9.4,-1.35) 32(-9.4,-1.35)
FPC_24P_0P5
  rect 0.3x1.3 smd: 1(-5.75,-1.351) 2(-5.25,-1.351) 3(-4.75,-1.351) 4(-4.25,-1.351) 5(-3.75,-1.351) 6(-3.25,-1.351) 7(-2.75,-1.351) 8(-2.25,-1.351) 9(-1.75,-1.351) 10(-1.25,-1.351) 11(-0.75,-1.351) 12(-0.25,-1.351) 13(0.25,-1.351) 14(0.75,-1.351) 15(1.25,-1.351) 16(1.75,-1.351) 17(2.25,-1.351) 18(2.75,-1.351) 19(3.25,-1.351) 20(3.75,-1.351) 21(4.25,-1.351) 22(4.75,-1.351) 23(5.25,-1.351) 24(5.75,-1.351)
  rect 1.6x2 smd: 25(7.45,1.351) 26(-7.45,1.351)
GH1P25_TH_2P
  rect 0.9x0.9 hole 0.5: 1(-0.625,0)
  round 0.9 hole 0.5: 2(0.625,0)
HDMI-SMD
  round 2 hole 2 unplated: (-6.05,-2) (7.2,1.5)
  round 0.8 hole 0.55: 1(5.3,0.5) 2(4.731,-0.5) 3(4.145,0.5) 4(3.575,-0.5) 5(2.99,0.5) 6(2.419,-0.5) 7(1.835,0.5) 8(1.263,-0.5) 9(0.68,0.5) 10(0.107,-0.5) 11(-0.475,0.5) 12(-1.049,-0.5) 13(-1.63,0.5) 14(-2.205,-0.5) 15(-2.785,0.5) 16(-3.361,-0.5) 17(-3.94,0.5) 18(-4.517,-0.5) 19(-5.095,0.5)
  oval 3.2x1.4 hole 2.7x0.9: G1(-6.05,3.25) G2(3.45,3.25) G3(-2.95,-3.25) G4(6.05,-3.25)
HY911130A
  round 3.25 hole 3.25 unplated: (-5.715,0) (5.715,0)
  round 1.6 hole 1: 1(5.72,-8.89) 2(4.45,-6.35) 3(3.18,-8.89) 4(1.91,-6.35) 5(0.64,-8.89) 6(-0.63,-6.35) 7(-1.9,-8.89) 8(-3.17,-6.35) 9(-4.44,-8.89) 10(-5.71,-6.35)
  round 1.8 hole 1.2: 11(6.625,4.9) 12(4.085,4.9) 13(-4.085,4.9) 14(-6.625,4.9)
  round 2.43 hole 1.83: 15(7.745,-3.05) 16(-7.745,-3.05)
L0603
  rect 0.8x0.8 smd: 1(-0.8,0) 2(0.8,0)
L2520
  rect 1.118x2.032 smd: 1(-0.959,0) 2(0.959,0)
L4520
  rect 1.4x2.3 smd: 1(-1.8,0) 2(1.8,0)
LED0603
  rect 0.93x0.98 smd: 1(0.77,0) 2(-0.77,0)
NANO_SIM
  round 0.9 hole 0.9 unplated: (-5,-5.49) (3.5,-5.49)
  rect 0.5x1.3 smd: 1(0.25,6.74) 2(-2.29,6.74) 3(-4.83,6.74) 4(2.47,6.74) 5(1.52,6.74) 6(-1.02,6.74) 7(-3.56,6.74)
  rect 1x2.1 smd: 8(-6.5,5.26) 9(6.5,5.26) 10(-6.5,-6.74) 11(6.5,-6.74)
NPTH_M3
  round 3.2 hole 3.2 unplated: (0,0)
PCIE_52P
  round 1.6 hole 1.6 unplated: (-12.5,0)
  round 1.1 hole 1.1 unplated: (12.5,0)
  rect 0.6x2 smd: 1(-11.8,-4.1) 2(-11.4,4.1) 3(-11,-4.1) 4(-10.6,4.1) 5(-10.2,-4.1) 6(-9.8,4.1) 7(-9.4,-4.1) 8(-9,4.1) 9(-8.6,-4.1) 10(-8.2,4.1) 11(-7.8,-4.1) 12(-7.4,4.1) 13(-7,-4.1) 14(-6.6,4.1) 15(-6.2,-4.1) 16(-5.8,4.1) 17(-2.2,-4.1) 18(-1.8,4.1) 19(-1.4,-4.1) 20(-1,4.1) 21(-0.6,-4.1) 22(-0.2,4.1) 23(0.2,-4.1) 24(0.6,4.1) 25(1,-4.1) 26(1.4,4.1) 27(1.8,-4.1) 28(2.2,4.1) 29(2.6,-4.1) 30(3,4.1) 31(3.4,-4.1) 32(3.8,4.1) 33(4.2,-4.1) 34(4.6,4.1) 35(5,-4.1) 36(5.4,4.1) 37(5.8,-4.1) 38(6.2,4.1) 39(6.6,-4.1) 40(7,4.1) 41(7.4,-4.1) 42(7.8,4.1) 43(8.2,-4.1) 44(8.6,4.1) 45(9,-4.1) 46(9.4,4.1) 47(9.8,-4.1) 48(10.2,4.1) 49(10.6,-4.1) 50(11,4.1) 51(11.4,-4.1) 52(11.8,4.1)
  rect 2.15x2.6 smd: 53(14.65,-3.5) 54(-14.65,-3.5)
PH-1X2-2P0_L
  rect 1.1x1.1 hole 0.7: 1(-1,0)
  round 1.1 hole 0.7: 2(1,0)
PH-1X4-2P0
  rect 1.1x1.1 hole 0.7: 1(-3,0)
  round 1.1 hole 0.7: 2(-1,0) 3(1,0) 4(3,0)
PH-1X6-2P0
  rect 1.1x1.1 hole 0.7: 1(-5,0)
  round 1.1 hole 0.7: 2(-3,0) 3(-1,0) 4(1,0) 5(3,0) 6(5,0)
QFN24
  rect 1x0.3 smd: 1(-2.1,1.25) 2(-2.1,0.75) 3(-2.1,0.25) 4(-2.1,-0.25) 5(-2.1,-0.75) 6(-2.1,-1.25) 13(2.1,-1.25) 14(2.1,-0.75) 15(2.1,-0.25) 16(2.1,0.25) 17(2.1,0.75) 18(2.1,1.25)
  rect 0.3x1 smd: 7(-1.25,-2.1) 8(-0.75,-2.1) 9(-0.25,-2.1) 10(0.25,-2.1) 11(0.75,-2.1) 12(1.25,-2.1) 19(1.25,2.1) 20(0.75,2.1) 21(0.25,2.1) 22(-0.25,2.1) 23(-0.75,2.1) 24(-1.25,2.1)
  rect 2x2 smd: 25(0,0)
QFP_40P_R
  oval 0.8x0.22 smd: 1(-2.5,1.8) 2(-2.5,1.4) 3(-2.5,1) 4(-2.5,0.6) 5(-2.5,0.2) 6(-2.5,-0.2) 7(-2.5,-0.6) 8(-2.5,-1) 9(-2.5,-1.4) 10(-2.5,-1.8) 21(2.5,-1.8) 22(2.5,-1.4) 23(2.5,-1) 24(2.5,-0.6) 25(2.5,-0.2) 26(2.5,0.2) 27(2.5,0.6) 28(2.5,1) 29(2.5,1.4) 30(2.5,1.8)
  oval 0.22x0.8 smd: 11(-1.8,-2.5) 12(-1.4,-2.5) 13(-1,-2.5) 14(-0.6,-2.5) 15(-0.2,-2.5) 16(0.2,-2.5) 17(0.6,-2.5) 18(1,-2.5) 19(1.4,-2.5) 20(1.8,-2.5) 31(1.8,2.5) 32(1.4,2.5) 33(1,2.5) 34(0.6,2.5) 35(0.2,2.5) 36(-0.2,2.5) 37(-0.6,2.5) 38(-1,2.5) 39(-1.4,2.5) 40(-1.8,2.5)
  rect 3x3 smd: 41(0,0)
R0402
  rect 0.599x0.599 smd: 1(-0.5,0) 2(0.5,0)
R0603
  rect 0.8x0.8 smd: 1(-0.8,0) 2(0.8,0)
RL-UM02WBS-8723BU
  oval 2x1 smd: 1(-6.3,3.97) 2(-6.3,1.97) 3(-6.3,-1.01) 4(-6.3,-3.17) 5(6.3,3.5) 6(6.3,0.97) 7(6.3,-2.53) 8(6.3,-5.33)
  oval 1x2 smd: 9(3.65,-6.9) 10(2.38,-6.9) 11(1.11,-6.9) 12(-0.16,-6.9) 13(-1.43,-6.9) 14(-2.7,-6.9)
SGDBF-05-80P-H30
  round 0.6 hole 0.6 unplated: (-10.7,-1.25) (10.7,-1.25)
  rect 0.25x2 smd: 1(9.75,-2) 2(9.75,2) 3(9.25,-2) 4(9.25,2) 5(8.75,-2) 6(8.75,2) 7(8.25,-2) 8(8.25,2) 9(7.75,-2) 10(7.75,2) 11(7.25,-2) 12(7.25,2) 13(6.75,-2) 14(6.75,2) 15(6.25,-2) 16(6.25,2) 17(5.75,-2) 18(5.75,2) 19(5.25,-2) 20(5.25,2) 21(4.75,-2) 22(4.75,2) 23(4.25,-2) 24(4.25,2) 25(3.75,-2) 26(3.75,2) 27(3.25,-2) 28(3.25,2) 29(2.75,-2) 30(2.75,2) 31(2.25,-2) 32(2.25,2) 33(1.75,-2) 34(1.75,2) 35(1.25,-2) 36(1.25,2) 37(0.75,-2) 38(0.75,2) 39(0.25,-2) 40(0.25,2) 41(-0.25,-2) 42(-0.25,2) 43(-0.75,-2) 44(-0.75,2) 45(-1.25,-2) 46(-1.25,2) 47(-1.75,-2) 48(-1.75,2) 49(-2.25,-2) 50(-2.25,2) 51(-2.75,-2) 52(-2.75,2) 53(-3.25,-2) 54(-3.25,2) 55(-3.75,-2) 56(-3.75,2) 57(-4.25,-2) 58(-4.25,2) 59(-4.75,-2) 60(-4.75,2) 61(-5.25,-2) 62(-5.25,2) 63(-5.75,-2) 64(-5.75,2) 65(-6.25,-2) 66(-6.25,2) 67(-6.75,-2) 68(-6.75,2) 69(-7.25,-2) 70(-7.25,2) 71(-7.75,-2) 72(-7.75,2) 73(-8.25,-2) 74(-8.25,2) 75(-8.75,-2) 76(-8.75,2) 77(-9.25,-2) 78(-9.25,2) 79(-9.75,-2) 80(-9.75,2)
SGDBM-05-80P-H10
  round 0.6 hole 0.6 unplated: (-10.7,-1.25) (10.7,-1.25)
  rect 0.25x2 smd: 1(-9.75,-2) 2(-9.75,2) 3(-9.25,-2) 4(-9.25,2) 5(-8.75,-2) 6(-8.75,2) 7(-8.25,-2) 8(-8.25,2) 9(-7.75,-2) 10(-7.75,2) 11(-7.25,-2) 12(-7.25,2) 13(-6.75,-2) 14(-6.75,2) 15(-6.25,-2) 16(-6.25,2) 17(-5.75,-2) 18(-5.75,2) 19(-5.25,-2) 20(-5.25,2) 21(-4.75,-2) 22(-4.75,2) 23(-4.25,-2) 24(-4.25,2) 25(-3.75,-2) 26(-3.75,2) 27(-3.25,-2) 28(-3.25,2) 29(-2.75,-2) 30(-2.75,2) 31(-2.25,-2) 32(-2.25,2) 33(-1.75,-2) 34(-1.75,2) 35(-1.25,-2) 36(-1.25,2) 37(-0.75,-2) 38(-0.75,2) 39(-0.25,-2) 40(-0.25,2) 41(0.25,-2) 42(0.25,2) 43(0.75,-2) 44(0.75,2) 45(1.25,-2) 46(1.25,2) 47(1.75,-2) 48(1.75,2) 49(2.25,-2) 50(2.25,2) 51(2.75,-2) 52(2.75,2) 53(3.25,-2) 54(3.25,2) 55(3.75,-2) 56(3.75,2) 57(4.25,-2) 58(4.25,2) 59(4.75,-2) 60(4.75,2) 61(5.25,-2) 62(5.25,2) 63(5.75,-2) 64(5.75,2) 65(6.25,-2) 66(6.25,2) 67(6.75,-2) 68(6.75,2) 69(7.25,-2) 70(7.25,2) 71(7.75,-2) 72(7.75,2) 73(8.25,-2) 74(8.25,2) 75(8.75,-2) 76(8.75,2) 77(9.25,-2) 78(9.25,2) 79(9.75,-2) 80(9.75,2)
SMA214-CA
  rect 2.1x1.8 smd: 1(-2.2,0) 2(2.2,0)
SMB-CA
  rect 2.4x2.8 smd: 1(-2.3,0) 2(2.3,0)
SMD4-6R80X2R50
  rect 0.8x1.2 smd: 1(1.905,0) 2(0.635,0) 3(-0.635,0) 4(-1.905,0)
SMTSO-M2R5
  round 6.2 hole 4.22: 1(0,0)
SOD523
  rect 0.6x0.7 smd: 1(-0.71,0) 2(0.71,0)
SOD-123
  rect 1.2x1.4 smd: 1(1.7,0) 2(-1.7,0)
SOIC8-208
  rect 1.778x0.635 smd: 1(-4,1.905) 2(-4,0.635) 3(-4,-0.635) 4(-4,-1.905) 5(4,-1.905) 6(4,-0.635) 7(4,0.635) 8(4,1.905)
SOIC16
  oval 2.032x0.61 smd: 1(-2.789,4.44) 2(-2.789,3.18) 3(-2.789,1.9) 4(-2.789,0.64) 5(-2.789,-0.64) 6(-2.789,-1.9) 7(-2.789,-3.18) 8(-2.789,-4.44) 9(2.789,-4.44) 10(2.789,-3.18) 11(2.789,-1.9) 12(2.789,-0.64) 13(2.789,0.64) 14(2.789,1.9) 15(2.789,3.18) 16(2.789,4.44)
SOP8
  oval 0.6x1.8 smd: 1(-1.905,-2.5) 2(-0.635,-2.5) 3(0.635,-2.5) 4(1.905,-2.5) 5(1.905,2.5) 6(0.635,2.5) 7(-0.635,2.5) 8(-1.905,2.5)
SOP-8
  oval 0.7x1.7 smd: 1(-1.905,-3.1) 2(-0.635,-3.1) 3(0.635,-3.1) 4(1.905,-3.1) 5(1.905,3.1) 6(0.635,3.1) 7(-0.635,3.1) 8(-1.905,3.1)
SOT23
  rect 0.914x0.914 smd: 1(-0.953,-0.991) 2(0.953,-0.991)
  rect 0.914x1.27 smd: 3(0,1.041)
SOT23-5
  rect 0.599x1.199 smd: 1(-0.95,-1.25) 2(0,-1.25) 3(0.95,-1.25) 4(0.95,1.25) 5(-0.95,1.25)
SOT23_6
  rect 0.7x0.9 smd: 1(-0.95,-1.2) 2(0,-1.2) 3(0.95,-1.2) 4(0.95,1.2) 5(0,1.2) 6(-0.95,1.2)
SOT563
  rect 0.3x0.45 smd: 1(-0.5,-0.675) 2(0,-0.675) 3(0.5,-0.675) 4(0.5,0.675) 5(0,0.675) 6(-0.5,0.675)
SOT-353
  rect 0.406x1.194 smd: 1(-0.65,-0.9) 2(0,-0.9) 3(0.65,-0.9) 4(0.65,0.9) 5(-0.65,0.9)
SW_3_2X4_2
  rect 1.1x0.7 smd: 1(-2.1,1.1) 2(2.1,1.1) 3(-2.1,-1.1) 4(2.1,-1.1)
T3R2-5R2_TOPSMT
  round 5.2 hole 3.2: 1(0,0)
TFCARD
  round 1.016 hole 1.016 unplated: (-4,0) (4,0)
  rect 0.7x1.6 smd: 1(3.2,10.5) 2(2.1,10.5) 3(1,10.5) 4(-0.1,10.5) 5(-1.2,10.5) 6(-2.3,10.5) 7(-3.4,10.5) 8(-4.5,10.5) 9(-5.6,10.5)
  rect 1.2x1.778 smd: 10(-6.8,10)
  rect 1.524x2.413 smd: 11(-6.8,0.4) 12(8.7,0.4)
  rect 1.778x1.778 smd: 13(7.8,10)
TYPE-C-31-M-12
  round 0.65 hole 0.65 unplated: (-2.89,-1.44) (2.89,-1.44)
  rect 0.3x2 smd: A1(-3.35,0.279) A4(-2.55,0.279) A5(-1.25,0.279) A6(-0.249,0.279) A7(0.249,0.279) A8(1.25,0.279) A9(2.55,0.279) A12(3.35,0.279) B1(3.05,0.279) B4(2.25,0.279) B5(1.75,0.279) B6(0.749,0.279) B7(-0.749,0.279) B8(-1.75,0.279) B9(-2.25,0.279) B12(-3.05,0.279)
  oval 1.1x1.7 hole 0.6x1.2: C1(-4.32,-5.1) C2(4.32,-5.1)
  oval 1.1x2.2 hole 0.6x1.7: C3(-4.32,-0.909) C4(4.32,-0.909)
UFL-3
  rect 1.05x1.05 smd: 1(0,-1.5)
  rect 1.05x2.2 smd: 2(-1.5,0) 3(1.5,0)
unnamed#2
  round 1.016 smd: 1(0,0)
USB3D0-AF-18P
  round 1.1 hole 0.7: 1(-3.5,-1.5) 2(-1,-1.5) 3(1,-1.5) 4(3.5,-1.5) 5(4,0) 6(2,0) 7(0,0) 8(-2,0) 9(-4,0) 10(-3.5,1.7) 11(-1,1.7) 12(1,1.7) 13(3.5,1.7) 14(4,3.2) 15(2,3.2) 16(0,3.2) 17(-2,3.2) 18(-4,3.2)
  round 3.2 hole 2.4: 19(6.57,-3.5) 20(6.57,2.18) 21(-6.57,2.18) 22(-6.57,-3.5)
USB-A-D
  round 1.651 hole 1: 1(3.5,-6.5) 2(1,-6.5) 3(-1,-6.5) 4(-3.5,-6.5) 7(3.5,-3.5) 8(1,-3.5) 9(-1,-3.5) 10(-3.5,-3.5)
  round 3.3 hole 2: 5(-6.55,-6.5) 6(6.55,-6.5) 11(-6.55,-0.7) 12(6.55,-0.7)
USON_10
  rect 0.3x0.55 smd: 1(-1,-0.4) 2(-0.5,-0.4) 4(0.5,-0.4) 5(1,-0.4) 6(1,0.4) 7(0.5,0.4) 9(-0.5,0.4) 10(-1,0.4)
  rect 0.4x0.55 smd: 3(0,-0.4) 8(0,0.4)
XH2P54-4P
  rect 1.45x1.45 hole 0.85: 1(-3.81,0)
  round 1.45 hole 0.85: 2(-1.27,0) 3(1.27,0) 4(3.81,0)
ZH1P5MM_TH_2P
  round 1.05 hole 0.65: 1(-0.75,0) 2(0.75,0)

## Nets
1V05_AVDD_PHY: C97.1 C98.1 C99.1 C100.1 R124.2 U16.3(AVDD10_2) U16.8(AVDD10_1) U16.38(AVDD10)
1V05_DVDD_PHY: C93.1 C94.1 C95.1 C96.1 R123.1 U16.21(DVDD10)
1V05_PHY: C79.1 C80.1 L4.2 R123.2 R124.1
1V8_DVDD_PHY: C101.1 C102.1 L7.1 R89.2 R90.1 R106.1 R119.1
3V3_AVDD_PHY: C89.1 C90.1 C91.1 L6.1 U16.11(AVDD33_1) U16.40(AVDD33)
3V3_DVDD_PHY: C85.1 C86.1 C87.1 L5.1 R91.2 R92.2 R107.2 R110.1 R118.2 R120.1 R122.2 U16.29(DVDD33)
3V3_EDP: C149.1 C150.1 J25.12 J25.13 J26.1 R188.1 R189.1 R190.1 U34.1(OUT)
3V3_IMAGE_1: C136.1 C137.1 J21.4 J21.5 R162.1 R166.1 U30.1(OUT)
3V3_IMAGE_2: C138.1 C139.1 J22.4 J22.5 R164.1 R168.1 U31.1(OUT)
3V3_OUT: C42.1 C43.1 J3.5 U6.1(OUT)
3V3_WLAN: C108.1 C109.1 Q7.3(DRAIN) U17.8(VCC3V3)
5V0_CAM_1: C141.1 C142.1 J23.1 J23.2 J23.3 U32.1(OUT)
5V0_CAM_2: C144.1 C145.1 J24.1 J24.2 J24.3 U33.1(OUT)
5V0_IMAGE_1: C134.1 C135.1 J21.1 J21.2 J21.3 U28.1(OUT)
5V0_IMAGE_2: C131.1 C132.1 J22.1 J22.2 J22.3 U29.1(OUT)
5V_OUT: C45.1 C46.1 J3.3 U7.1(OUT)
12V_EDP: C152.1 C153.1 J25.26 J25.27 J25.28 J25.29 Q12.3(DRAIN)
12V_OUT: C39.1 C40.1 J3.1 Q5.3(DRAIN)
GND: C1.2 C2.2 C3.2 C4.2 C5.2 C6.2 C9.2 C10.2 C11.2 C12.2 C13.2 C14.2 C15.2 C16.2 C17.2 C18.1 C21.2 C22.2 C23.2 C24.2 C25.2 C26.2 C27.1 C30.2 C31.2 C32.2 C33.2 C34.2 C35.2 C36.2 C37.1 C39.2 C40.2 C41.2 C42.2 C43.2 C44.2 C45.2 C46.2 C47.2 C48.2 C49.2 C50.2 C51.2 C52.2 C53.2 C54.2 C55.2 C56.2 C57.2 C58.2 C59.2 C60.2 C61.2 C62.2 C63.2 C64.2 C65.2 C66.2 C67.2 C68.2 C71.2 C72.2 C73.2 C74.2 C75.2 C77.2 C78.2 C79.2 C80.2 C81.2 C82.2 C83.2 C84.2 C85.2 C86.2 C87.2 C88.2 C89.2 C90.2 C91.2 C92.2 C93.2 C94.2 C95.2 C96.2 C97.2 C98.2 C99.2 C100.2 C101.2 C102.2 C103.2 C105.2 C106.2 C108.2 C109.2 C110.2 C111.2 C114.2 C115.2 C116.2 C117.2 C118.1 C119.2 C120.2 C121.2 C122.2 C123.2 C124.2 C125.2 C126.2 C127.2 C128.2 C129.2 C130.2 C131.2 C132.2 C133.2 C134.2 C135.2 C136.2 C137.2 C138.2 C139.2 C140.2 C141.2 C142.2 C143.2 C144.2 C145.2 C148.2 C149.2 C150.2 C152.2 C153.2 C156.2 C157.2 C158.2 C159.2 C160.2 C161.2 C162.2 C163.2 C164.2 C167.2 C168.2 C169.2 C170.2 C171.2 C172.2 C173.2 C177.2 CN1.2 CN1.3 D1.2 D2.2(A) D3.1 D4.1 D5.1 D6.1 D7.1 D8.1 D10.1 D11.1 D12.1 D13.1 D14.1 D15.1 D16.1 D17.1 D18.1 D19.1 D20.1 D21.1 D24.1 D25.1 D26.1 D27.1 D30.1 D31.1 D33.1 D34.1 D35.1 D36.1 D37.1 D38.1 D39.1 D41.1 D42.1 D43.1 D44.1 D45.1 D46.1 D47.1 D48.1 D49.1 D50.1 D51.1 D52.1 D53.1 D54.1 J1.1 J1.2 J1.3 J1.5 J2.2 J3.2 J3.4 J3.6 J4.7 J4.8 J4.9 J4.10 J4.16 J4.20 J4.23 J4.26 J4.31 J4.32 J4.40 J4.49 J4.50 J4.56 J4.66 J4.67 J4.73 J4.76 J5.1 J5.2 J5.3 J5.13 J5.18 J5.23 J5.24 J5.26 J5.29 J5.36 J5.39 J5.49 J5.54 J5.55 J5.65 J5.66 J5.79 J5.80 J6.1 J6.2 J6.8 J6.11 J6.14 J6.27 J6.30 J6.40 J6.41 J6.55 J6.58 J6.64 J6.68 J6.69 J6.75 J6.79 J7.1 J7.2 J7.12 J7.23 J7.26 J7.33 J7.40 J7.54 J7.58 J7.64 J7.69 J7.70 J7.71 J7.73 J7.75 J7.76 J7.77 J7.78 J7.79 J7.80 J8.1 J9.4 J10.2 J11.2 J11.5 J12.6(VSS) J12.10(GND10) J12.11(GND11) J12.12(GND12) J12.13(GND13) J17.10(CHS) J17.15(SH) J17.16(SH1) J18.4(GND1) J18.7(GND2) J18.13(GND1) J18.16(NC3) J18.19(SH1) J18.20(SH2) J18.21(SH1) J18.22(SH2) J19.A1(GND1) J19.A12(GND2) J19.B1(GND4) J19.B12(GND3) J20.4(GND) J20.5(SH1) J20.6(SH2) J20.10(GND) J20.11(SH1) J20.12(SH2) J21.6 J21.7 J21.8 J21.16 J21.19 J21.22 J21.25 J21.28 J21.31(SH1) J21.32(SH2) J22.6 J22.7 J22.8 J22.16 J22.19 J22.22 J22.25 J22.28 J22.31(SH1) J22.32(SH2) J23.4 J23.18 J23.21 J23.23 J23.24 J23.25(SH1) J23.26(SH2) J24.4 J24.23 J24.24 J24.25(SH1) J24.26(SH2) J25.2 J25.5 J25.8 J25.11 J25.15 J25.16 J25.18 J25.19 J25.20 J25.21 J25.31(SH1) J25.32(SH2) J26.6 J27.4(GND9) J27.9(GND1) J27.15(GND2) J27.18(GND10) J27.21(GND3) J27.26(GND11) J27.27(GND4) J27.29(GND5) J27.34(GND12) J27.35(GND6) J27.37(GND7) J27.40(GND13) J27.43(GND8) J27.50(GND14) J27.53 J27.54 J32.4 J33.4 J34.4 J35.4 L8.2 L9.2 Q2.2(EMITTER) Q3.2(EMITTER) Q6.2(EMITTER) Q13.2(EMITTER) R2.2 R5.2 R6.2 R8.2 R13.2 R15.2 R18.2 R21.2 R22.2 R25.2 R29.2 R31.2 R33.2 R35.2 R75.2 R76.2 R77.2 R78.2 R98.2 R103.2 R104.2 R105.2 R113.2 R114.2 R115.2 R116.2 R121.1 R143.2 R147.2 R150.2 R152.2 R154.2 R172.2 R173.2 R174.2 R175.2 R181.2 R187.2 R191.1 R194.2 R197.2 R203.2 R216.2 R217.2 R218.2 SS1.1(NC_1) SS2.1(NC_1) SS3.1(NC_1) SS4.1(NC_1) SS5.1(NC_1) SS6.1(NC_1) SW1.1(A1) SW1.2(A2) SW2.1(A1) SW2.2(A2) SW3.1(A1) SW3.2(A2) SW4.1(A1) SW4.2(A2) U1.2(GND) U2.2(GND) U3.1(GND) U4.1(GND) U5.1(GND) U6.2(GND) U7.2(GND) U8.4(GND) U9.1(\\O\E) U9.3(GND) U10.1(\\O\E) U10.3(GND) U11.1(GND1) U11.4(GND2) U12.4(GND) U13.15(GND) U14.5(GND) U15.5(GND) U16.41(GND) U17.1(GND#1) U17.5(GND#5) U18.3(GND1) U18.8(GND2) U19.3(GND1) U19.8(GND2) U20.3(GND1) U20.8(GND2) U21.2(GND) U22.25(VSS) U23.2(GND) U24.2(GND) U25.2 U25.5 U25.8 U25.11 U25.17 U26.3(GND1) U26.8(GND2) U27.3(GND1) U27.8(GND2) U28.2(GND) U29.2(GND) U30.2(GND) U31.2(GND) U32.2(GND) U33.2(GND) U34.2(GND) U35.1(GND) U36.5(GND) U36.8(SH1) U36.9(SH2) U36.10(SH3) U36.11(SH4) U37.2 Y1.2(GND1) Y1.4(GND2) Y2.2(GND1) Y2.4(GND2)
VCC3V3_SD: C51.1 C71.1 C72.1 J4.15 J4.17 J12.4(VDD)
VCC3V3_SYS: C8.1 C15.1 C16.1 C17.1 L1.2 R4.1 U1.5(IN) U6.5(IN) U30.5(IN) U31.5(IN) U34.5(IN)
VCC5V0_SYS: C20.1 C24.1 C25.1 C26.1 C47.1 C48.1 J4.1 J4.2 J4.3 J4.4 J4.5 J4.6 L2.2 R11.1 R16.1 U2.5(IN) U28.5(IN) U29.5(IN) U32.5(IN) U33.5(IN)
VCC5V0_SYS_2: C29.1 C34.1 C35.1 C36.1 L3.2 R10.1 R20.1 U7.5(IN) U21.5(IN) U23.5(IN) U24.5(IN)
VCC5V0_USB20_HOST: C110.1 C111.1 C114.1 C115.1 J20.1(VBUS) J20.7(VBUS) U21.1(OUT)
VCC5V0_USB30_HOST: C120.1 C121.1 J18.1(VBUS) J18.10(VBUS) U23.1(OUT)
VCC_1V8: C49.1 C54.1 C55.1 C103.1 J4.11 J4.13 L7.2 R36.1 R37.1 U8.8(VCC)
VCC_12V: C1.1 C2.1 C3.1 C12.1 C13.1 C14.1 C21.1 C22.1 C23.1 C31.1 C32.1 C33.1 C38.1 C151.1 C156.1 C157.1 C158.1 D1.1 F1.2 R7.1 R9.1 R14.1 R23.1 R26.1 R27.1 R193.1 R195.1 U3.3(VIN) U4.3(VIN) U5.3(VIN) U35.3(VIN)
VCC_RTC: J4.18 R51.2
VCCA_1V8: C50.1 J4.12 J4.14 R34.1 R227.2
VCCIO_ACODEC: C52.1 C172.1 C177.1 J4.19 J4.21 R212.1 R214.1
VDD_3V3: C5.1 C6.1 C57.1 C59.1 C67.1 C73.1 C74.1 C75.1 C88.1 C92.1 C107.1 C125.1 D9.2 D22.2 D23.2 J32.1 J33.1 J34.1 J35.1 L5.2 L6.2 LED2.2(ANODE) LED3.2(ANODE) LED4.2(ANODE) Q7.2(SOURCE) R38.1 R42.1 R44.1 R47.2 R52.1 R53.1 R54.1 R55.1 R67.1 R68.1 R69.1 R70.1 R127.1 R151.1 R155.1 R156.1 R158.1 R163.1 R165.1 R167.1 R169.1 U1.1(OUT) U9.5(VCC) U10.5(VCC) U13.16(VCC) U14.8(VCC) U15.8(VCC)
VDD_5V: C10.1 C11.1 D32.2 Q8.1(GATE) U2.1(OUT)
B_DM1: J18.11(D-) R129.1 U18.5(D2-) U18.6(NC4)
B_DM2: J20.8(D-) R138.1 U20.4(D2+) U20.7(NC3)
B_DM3: J20.2(D-) R131.1 U20.1(D1+) U20.10(NC1)
B_DP1: J18.12(D+) R130.1 U18.4(D2+) U18.7(NC3)
B_DP2: J20.9(D+) R139.1 U20.5(D2-) U20.6(NC4)
B_DP3: J20.3(D+) R132.1 U20.2(D1-) U20.9(NC2)
BD_CH3: C53.1 J6.20 R34.2 R35.1
CAM0_NRST: J7.35 J23.22
CAM0_PWDN: J5.56 J23.15
CAM0_PWR_EN: J6.78 R179.1
CAM1_NRST: J7.41 J24.22
CAM1_PWDN: J7.63 J24.15
CAM1_PWR_EN: J5.12 R186.1
CC1: D29.2 J19.A5(CC1)
CC2: D29.1 J19.B5(CC2)
CSI_RX_D2N_S0: J23.17 R178.2
CSI_RX_D2N_S1: J24.12 R180.2
CSI_RX_D2P_S0: J23.16 R176.2
CSI_RX_D2P_S1: J24.11 R177.2
CSI_RX_D3N_S0: J23.20 R184.2
CSI_RX_D3N_S1: J24.8 R185.2
CSI_RX_D3P_S0: J23.19 R182.2
CSI_RX_D3P_S1: J24.7 R183.2
CTP0_INT: J6.65 J21.11 R162.2
